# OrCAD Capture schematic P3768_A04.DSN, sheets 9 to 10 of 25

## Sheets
9 0016_USB3.1 Type-A x2 [B]: size Custom
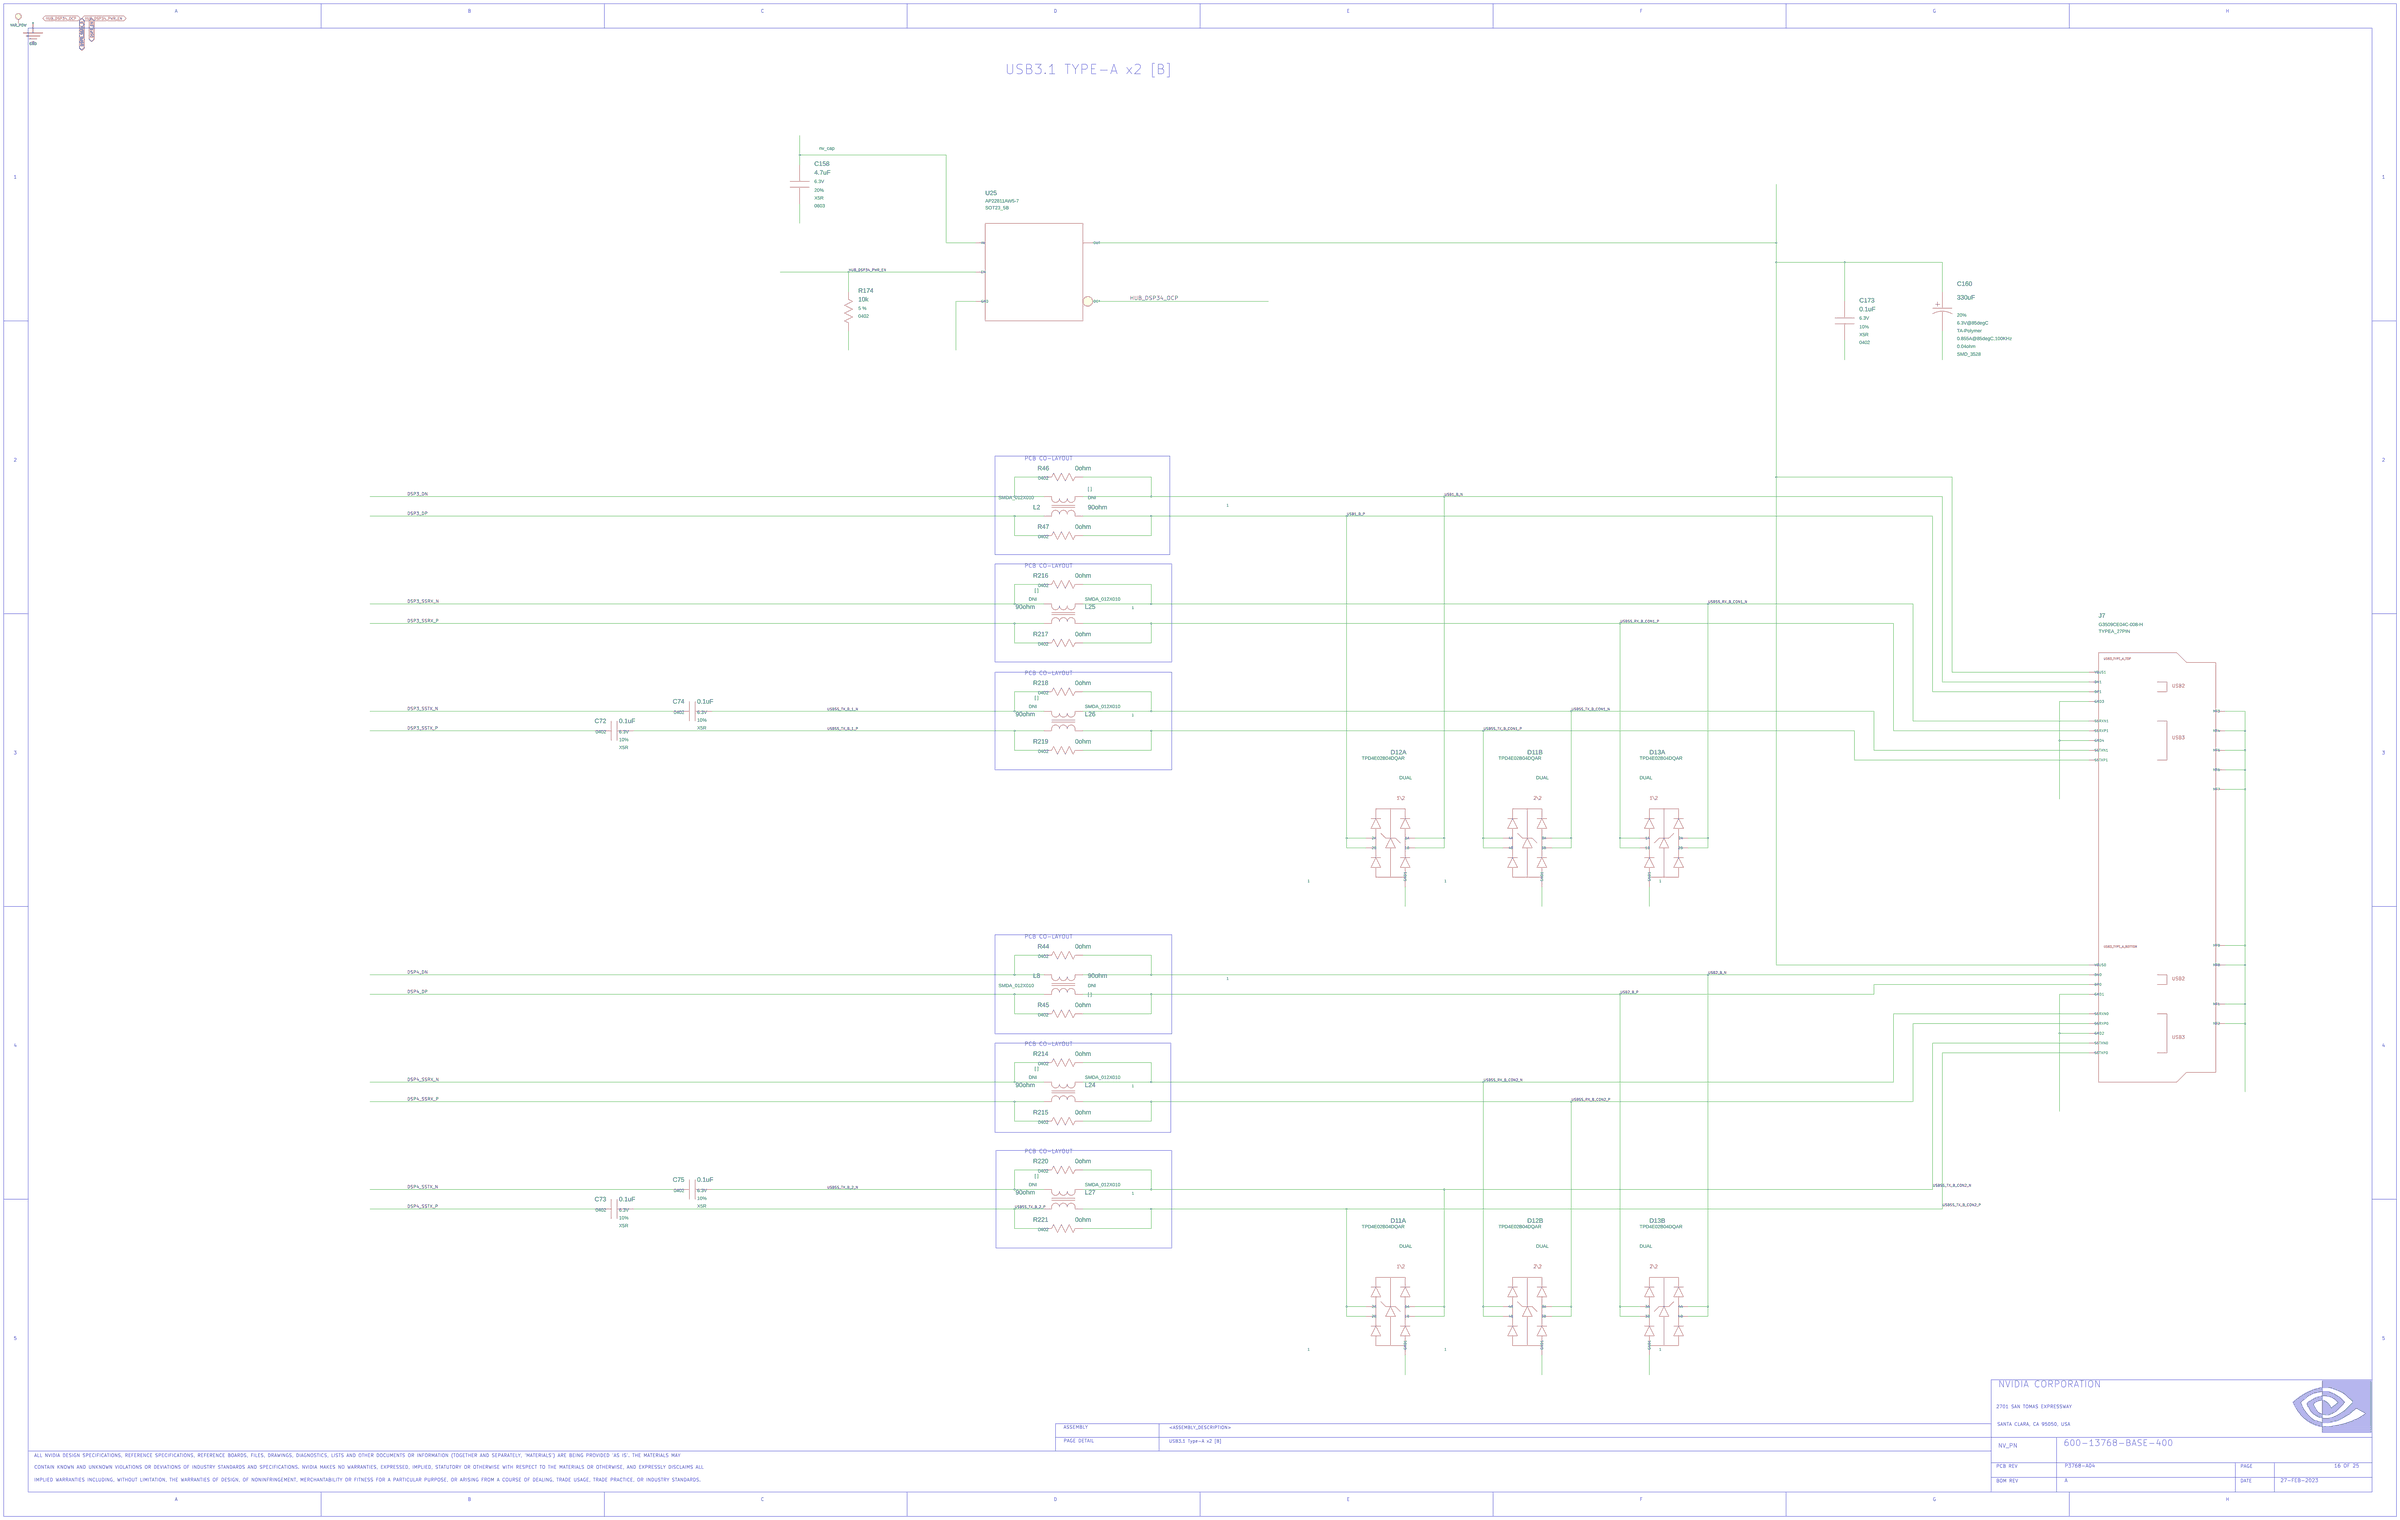
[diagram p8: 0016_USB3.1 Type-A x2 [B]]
10 0015_USB3.1 Type-A x2 [A]: size Custom
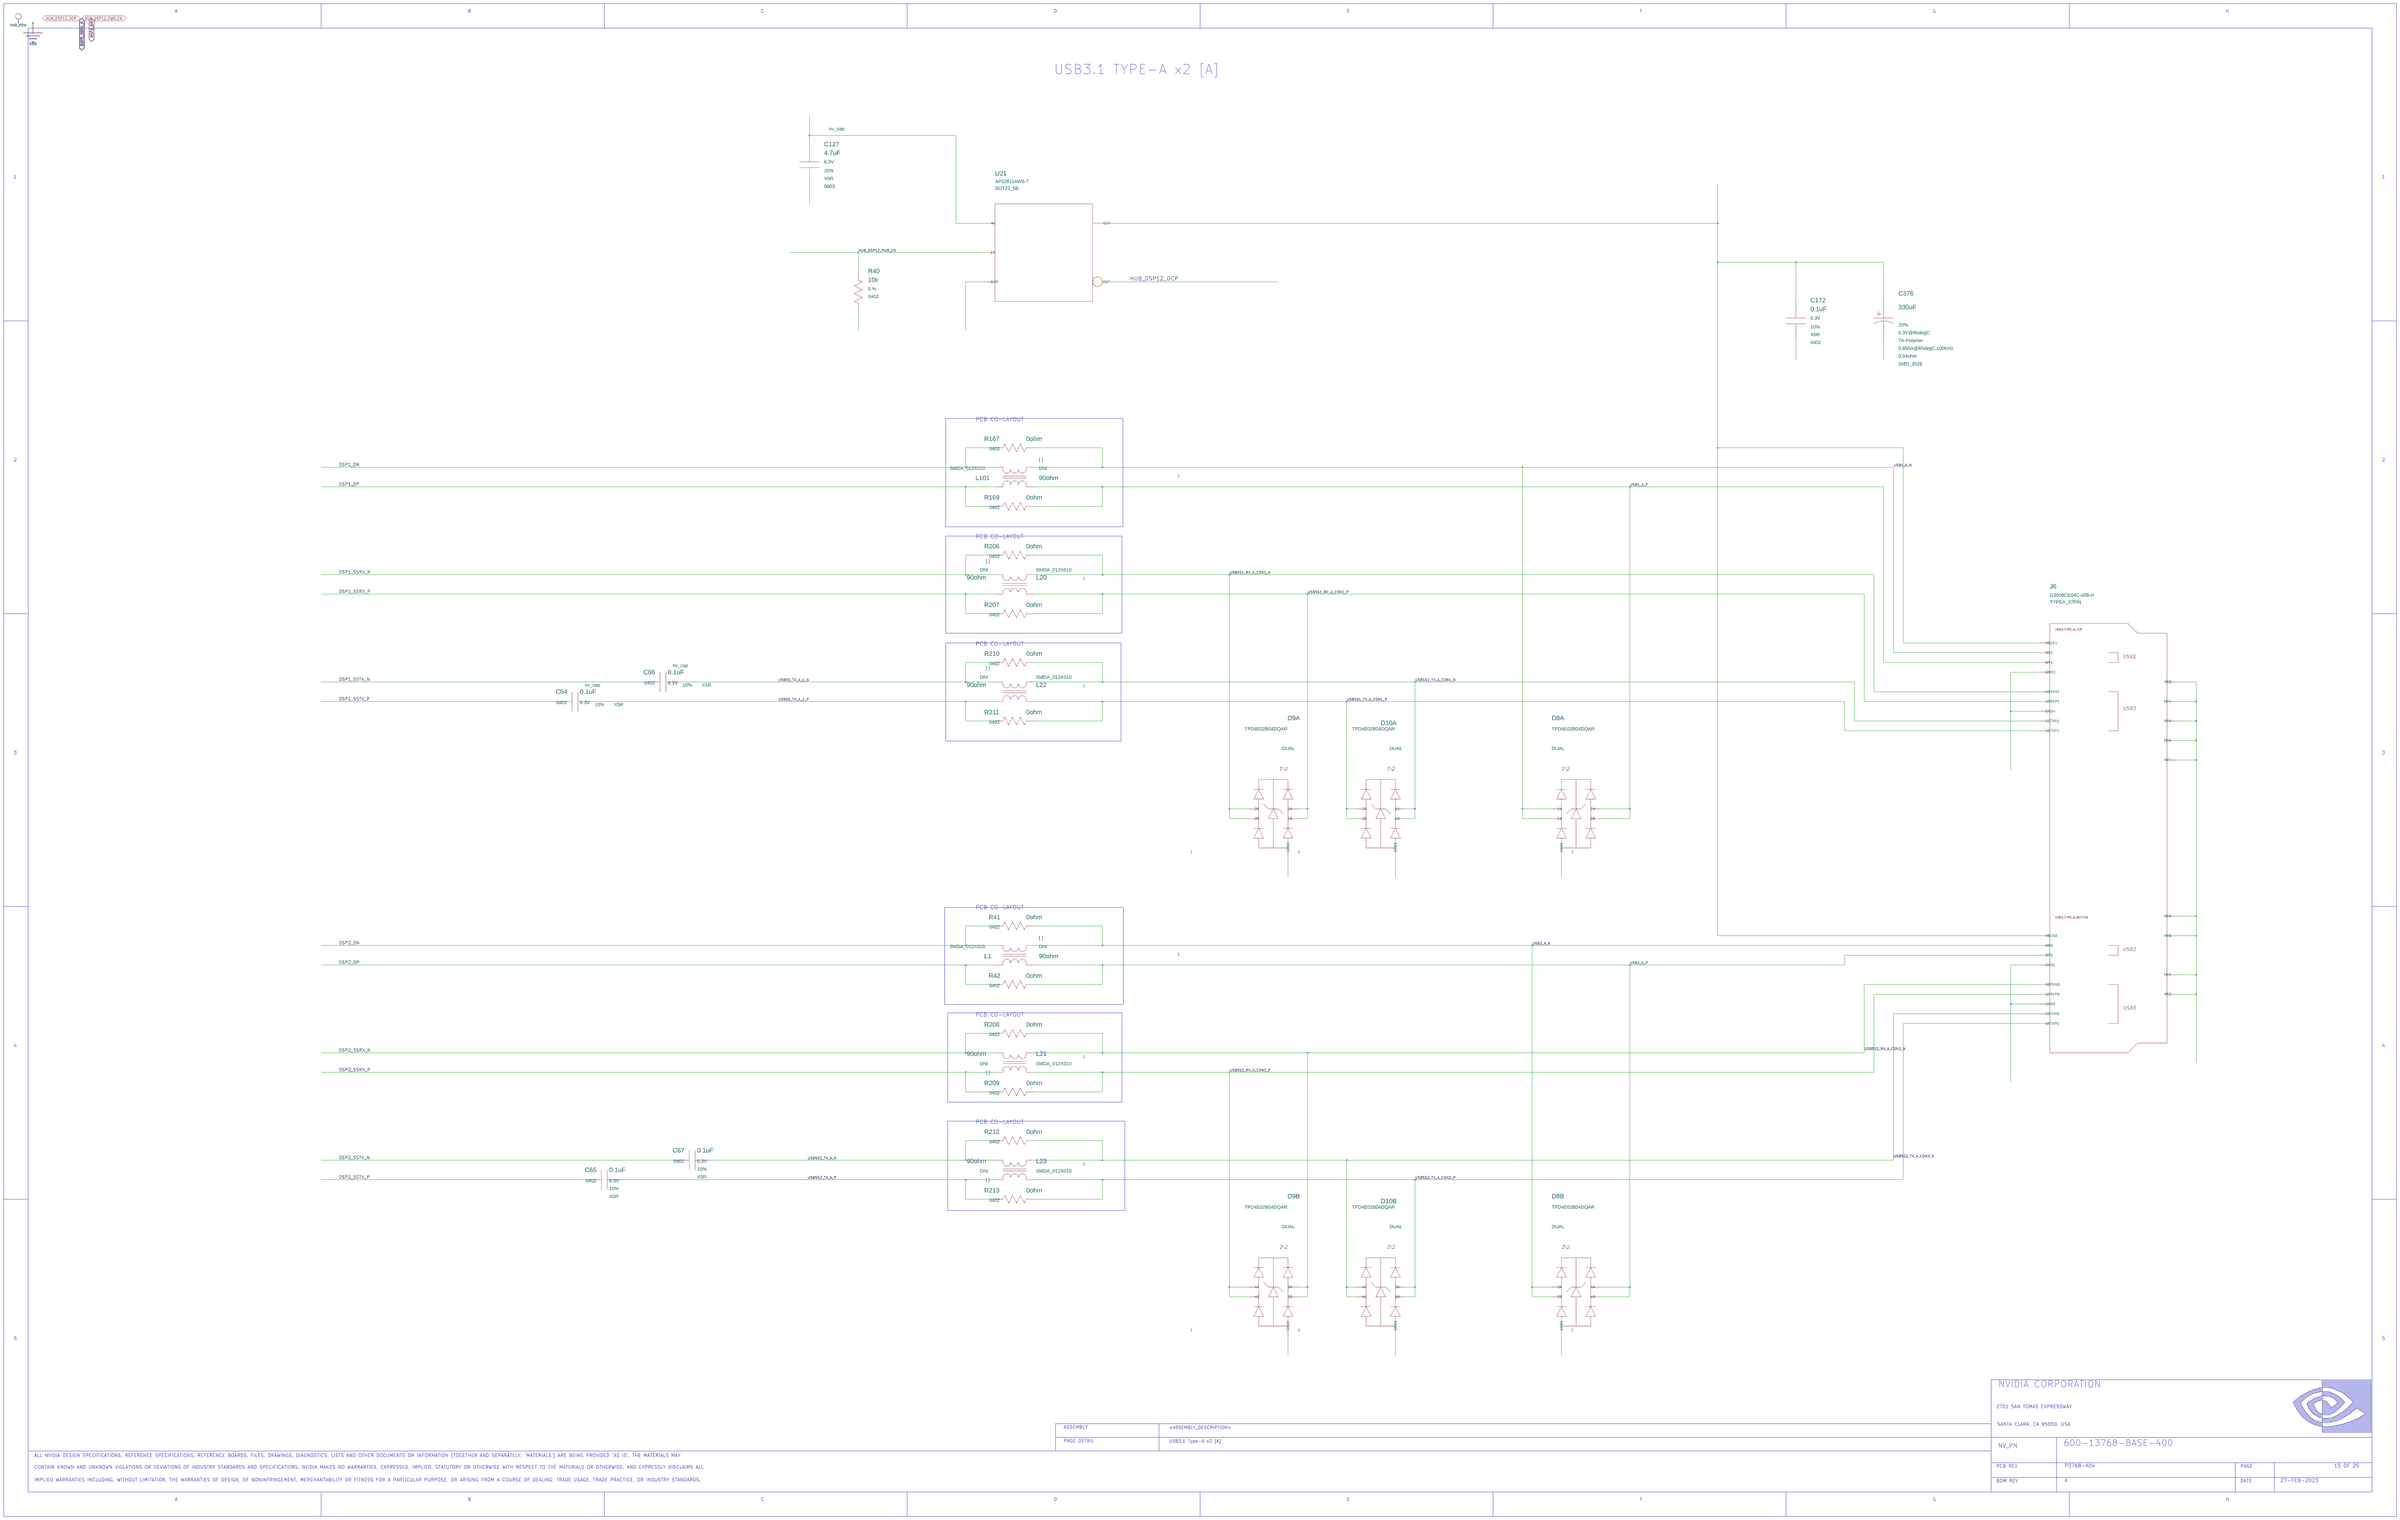
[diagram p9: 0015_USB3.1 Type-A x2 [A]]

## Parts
sheet 0015_USB3.1 Type-A x2 [A]
C64  0.1uF  [0402]
C65  0.1uF  [0402]
C66  0.1uF  [0402]
C67  0.1uF  [0402]
C127  4.7uF  [0603]
C172  0.1uF  [0402]
C376  330uF  [CAP_SMD_3528]
D8  D_ESD_DIFFPAIR  [TSLP10_P050_025X010]  (sections A,B)
D9  D_ESD_DIFFPAIR  [TSLP10_P050_025X010]  (sections A,B)
D10  D_ESD_DIFFPAIR  [TSLP10_P050_025X010]  (sections A,B)
J6  CON_USB3  [CON_USB3_024_SMT_RA_F_138X174]
L1  90ohm  [IND_NONRKO_SMD_012X010]
L20  90ohm  [IND_NONRKO_SMD_012X010]
L21  90ohm  [IND_NONRKO_SMD_012X010]
L22  90ohm  [IND_NONRKO_SMD_012X010]
L23  90ohm  [IND_NONRKO_SMD_012X010]
L101  90ohm  [IND_NONRKO_SMD_012X010]
R40  10k  [0402]
R41  0ohm  [0402]
R42  0ohm  [0402]
R167  0ohm  [0402]
R169  0ohm  [0402]
R206  0ohm  [0402]
R207  0ohm  [0402]
R208  0ohm  [0402]
R209  0ohm  [0402]
R210  0ohm  [0402]
R211  0ohm  [0402]
R212  0ohm  [0402]
R213  0ohm  [0402]
U21  U_SW_LOAD  [SOT23_5_B]
sheet 0016_USB3.1 Type-A x2 [B]
C72  0.1uF  [0402]
C73  0.1uF  [0402]
C74  0.1uF  [0402]
C75  0.1uF  [0402]
C158  4.7uF  [0603]
C160  330uF  [CAP_SMD_3528]
C173  0.1uF  [0402]
D11  D_ESD_DIFFPAIR  [TSLP10_P050_025X010]  (sections A,B)
D12  D_ESD_DIFFPAIR  [TSLP10_P050_025X010]  (sections A,B)
D13  D_ESD_DIFFPAIR  [TSLP10_P050_025X010]  (sections A,B)
J7  CON_USB3  [CON_USB3_024_SMT_RA_F_138X174]
L2  90ohm  [IND_NONRKO_SMD_012X010]
L8  90ohm  [IND_NONRKO_SMD_012X010]
L24  90ohm  [IND_NONRKO_SMD_012X010]
L25  90ohm  [IND_NONRKO_SMD_012X010]
L26  90ohm  [IND_NONRKO_SMD_012X010]
L27  90ohm  [IND_NONRKO_SMD_012X010]
R44  0ohm  [0402]
R45  0ohm  [0402]
R46  0ohm  [0402]
R47  0ohm  [0402]
R174  10k  [0402]
R214  0ohm  [0402]
R215  0ohm  [0402]
R216  0ohm  [0402]
R217  0ohm  [0402]
R218  0ohm  [0402]
R219  0ohm  [0402]
R220  0ohm  [0402]
R221  0ohm  [0402]
U25  U_SW_LOAD  [SOT23_5_B]

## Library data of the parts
C64 = C: ASSEMBLY: USB3_TYPEA; CDS_LIB: discrete; CDS_PART_NAME: C_0402-0.1UF,X5R,10%,6.3V,039-0007-000; CDS_PHYS_PART_NAME: C_0402-0.1UF,X5R,10%,6.3V,039-0007-000-0.1UF,039-0007-000; CDS_SEC: 1; DEVICE_TYPENAME: C_0402-01UFX5R1063V039-0007-000-01UF039-0007-000; DRAWING: @P3768_A04_LIB.P3768_A04(SCH_1):PAGE15; MAT: X5R; MAX_VOLTAGE: 6.3V; NV_PN: 039-0007-000; PATH: I101; PHYS_PAGE: 15; PSPICETEMPLATE: X^@REFDES  %1    %2   @NV_PN; ROT: 0; SEC: 1; SIGNAL_MODEL: nv_cap; TOL: 10%; VER: 2; XY: (-9200,4050)
C65 = C: ASSEMBLY: USB3_TYPEA; CDS_LIB: discrete; CDS_PART_NAME: C_0402-0.1UF,X5R,10%,6.3V,039-0007-000; CDS_PHYS_PART_NAME: C_0402-0.1UF,X5R,10%,6.3V,039-0007-000-0.1UF,039-0007-000; CDS_SEC: 1; DEVICE_TYPENAME: C_0402-01UFX5R1063V039-0007-000-01UF039-0007-000; DRAWING: @P3768_A04_LIB.P3768_A04(SCH_1):PAGE15; MAT: X5R; MAX_VOLTAGE: 6.3V; NV_PN: 039-0007-000; PATH: I91; PHYS_PAGE: 15; ROT: 0; SEC: 1; SIGNAL_MODEL: nv_cap; TOL: 10%; VER: 2; XY: (-9050,1600)
C66 = C: ASSEMBLY: USB3_TYPEA; CDS_LIB: discrete; CDS_PART_NAME: C_0402-0.1UF,X5R,10%,6.3V,039-0007-000; CDS_PHYS_PART_NAME: C_0402-0.1UF,X5R,10%,6.3V,039-0007-000-0.1UF,039-0007-000; CDS_SEC: 1; DEVICE_TYPENAME: C_0402-01UFX5R1063V039-0007-000-01UF039-0007-000; DRAWING: @P3768_A04_LIB.P3768_A04(SCH_1):PAGE15; MAT: X5R; MAX_VOLTAGE: 6.3V; NV_PN: 039-0007-000; PATH: I105; PHYS_PAGE: 15; PSPICETEMPLATE: X^@REFDES  %1    %2   @NV_PN; ROT: 0; SEC: 1; SIGNAL_MODEL: nv_cap; TOL: 10%; VER: 2; XY: (-8750,4150)
C67 = C: ASSEMBLY: USB3_TYPEA; CDS_LIB: discrete; CDS_PART_NAME: C_0402-0.1UF,X5R,10%,6.3V,039-0007-000; CDS_PHYS_PART_NAME: C_0402-0.1UF,X5R,10%,6.3V,039-0007-000-0.1UF,039-0007-000; CDS_SEC: 1; DEVICE_TYPENAME: C_0402-01UFX5R1063V039-0007-000-01UF039-0007-000; DRAWING: @P3768_A04_LIB.P3768_A04(SCH_1):PAGE15; MAT: X5R; MAX_VOLTAGE: 6.3V; NV_PN: 039-0007-000; PATH: I90; PHYS_PAGE: 15; ROT: 0; SEC: 1; SIGNAL_MODEL: nv_cap; TOL: 10%; VER: 2; XY: (-8600,1700)
C127 = C#1: ASSEMBLY: USB3_TYPEA; CDS_LIB: discrete; CDS_PART_NAME: C_0603-4.7UF,X5R,20%,6.3V,032-2124-000; CDS_PHYS_PART_NAME: C_0603-4.7UF,X5R,20%,6.3V,032-2124-000-032-2124-000,4.7UF; CDS_SEC: 1; CHIPS_PART_NAME: C; DEVICE_TYPENAME: C_0603-47UFX5R2063V032-2124-000-032-2124-00047UF; DRAWING: @P3768_A04_LIB.P3768_A04(SCH_1):PAGE15; MAT: X5R; MAX_VOLTAGE: 6.3V; NV_PN: 032-2124-000; PATH: I40; PHYS_PAGE: 15; PSPICETEMPLATE: X^@REFDES  %1    %2   @NV_PN; ROT: 0; SEC: 1; SIGNAL_MODEL: nv_cap; TOL: 20%; VER: 1; XY: (-8000,6800)
C172 = C#1: ASSEMBLY: USB3_TYPEA; CDS_LIB: discrete; CDS_PART_NAME: C_0402-0.1UF,X5R,10%,6.3V,039-0007-000; CDS_PHYS_PART_NAME: C_0402-0.1UF,X5R,10%,6.3V,039-0007-000-0.1UF,039-0007-000; CDS_SEC: 1; CHIPS_PART_NAME: C; DEVICE_TYPENAME: C_0402-01UFX5R1063V039-0007-000-01UF039-0007-000; DRAWING: @P3768_A04_LIB.P3768_A04(SCH_1):PAGE15; MAT: X5R; MAX_VOLTAGE: 6.3V; NV_PN: 039-0007-000; PATH: I65; PHYS_PAGE: 15; PSPICETEMPLATE: X^@REFDES  %1    %2   @NV_PN; ROT: 0; SEC: 1; SIGNAL_MODEL: nv_cap; TOL: 10%; VER: 1; XY: (-2950,6000)
C376 = C_POL: ASSEMBLY: USB3_TYPEA; CDS_LIB: discrete; CDS_PART_NAME: C_POL_SMD_3528-330UF,TA-POLYMER,20%,6.3V@85DEGC,0.04OHM,9.999UH,0.855A@85DEGC,100KHZ,032-0696-000; CDS_PHYS_PART_NAME: C_POL_SMD_3528-330UF,TA-POLYMER,20%,6.3V@85DEGC,0.04OHM,9.999UH,0.855A@85DEGC,100KHZ,032-0696-000-032-0696-000,330UF; CDS_SEC: 1; DEVICE_TYPENAME: C_POL_SMD_3528-330UFTA-POLYMER2063V85DEGC004OHM9999UH0855A85DEGC100KHZ032-0696-000-032-0696-000330UF; DRAWING: @P3768_A04_LIB.P3768_A04(SCH_1):PAGE15; ESL: 9.999uH; ESR: 0.04ohm; MAT: TA-Polymer; MAX_VOLTAGE: 6.3V@85degC; NV_PN: 032-0696-000; PACK_TYPE: SMD_3528; PATH: I99; PHYS_PAGE: 15; PSPICETEMPLATE: X^@REFDES  %1    %2   @NV_PN; RIPPLE_CURRENT: 0.855A@85degC,100KHz; ROT: 0; SEC: 1; SIGNAL_MODEL: nv_capp; TOL: 20%; VER: 1; XY: (-2500,6000)
D8 = D_ESD_DIFFPAIR: ASSEMBLY: USB3_TYPEA; BREAKDOWN_VOLTAGE_MIN_TYP: 6.7V; CAPACITANCE_MAX_TYP: 0.37pF; CDS_LIB: discrete; CDS_PART_NAME: D_ESD_DIFFPAIR_DUAL-TPD4E02B04DQAR,2 DIFFPAIR,BI-DIRECTIONAL,6V,0.01UA,6.7V,8V@40A,0.37PF,090-0296-000; CDS_PHYS_PART_NAME: D_ESD_DIFFPAIR_DUAL-TPD4E02B04DQAR,2 DIFFPAIR,BI-DIRECTIONAL,6V,0.01UA,6.7V,8V@40A,0.37PF,090-0296-000-090-0296-000; CDS_SEC: 1; CLAMPING_VOLTAGE: 8V@40A; CONFIGURATION: 2 Diffpair; CaptureCellPackProp: D_ESD_DIFFPAIRA; DEVICE_TYPENAME: D_ESD_DIFFPAIR_DUAL-TPD4E02B04DQAR2DIFFPAIRBI-DIRECTIONAL6V001UA67V8V40A037PF090-0296-000-090-0296-000; DRAWING: @P3768_A04_LIB.P3768_A04(SCH_1):PAGE15; MAX_REVERSE_LEAKAGE_CURRENT: 0.01uA; MAX_REVERSE_VOLTAGE: 6V; NO_XNET_CONNECTION: 1; NV_NAME: TPD4E02B04DQAR; NV_PN: 090-0296-000; PACK_TYPE: DUAL; PATH: I24; PHYS_PAGE: 15; POLARITY: Bi-Directional; ROT: 0; SEC: 1; SEC_TYPE: DUAL; VER: 1; XY: (-4100,3500)
D9 = D_ESD_DIFFPAIR: ASSEMBLY: USB3_TYPEA; BREAKDOWN_VOLTAGE_MIN_TYP: 6.7V; CAPACITANCE_MAX_TYP: 0.37pF; CDS_LIB: discrete; CDS_PART_NAME: D_ESD_DIFFPAIR_DUAL-TPD4E02B04DQAR,2 DIFFPAIR,BI-DIRECTIONAL,6V,0.01UA,6.7V,8V@40A,0.37PF,090-0296-000; CDS_PHYS_PART_NAME: D_ESD_DIFFPAIR_DUAL-TPD4E02B04DQAR,2 DIFFPAIR,BI-DIRECTIONAL,6V,0.01UA,6.7V,8V@40A,0.37PF,090-0296-000-090-0296-000; CDS_SEC: 1; CLAMPING_VOLTAGE: 8V@40A; CONFIGURATION: 2 Diffpair; CaptureCellPackProp: D_ESD_DIFFPAIRA; DEVICE_TYPENAME: D_ESD_DIFFPAIR_DUAL-TPD4E02B04DQAR2DIFFPAIRBI-DIRECTIONAL6V001UA67V8V40A037PF090-0296-000-090-0296-000; DRAWING: @P3768_A04_LIB.P3768_A04(SCH_1):PAGE15; MAX_REVERSE_LEAKAGE_CURRENT: 0.01uA; MAX_REVERSE_VOLTAGE: 6V; NO_XNET_CONNECTION: 1; NV_NAME: TPD4E02B04DQAR; NV_PN: 090-0296-000; PACK_TYPE: DUAL; PATH: I33; PHYS_PAGE: 15; POLARITY: Bi-Directional; ROT: 2; SEC: 1; VER: 1; XY: (-5600,3500)
D10 = D_ESD_DIFFPAIR: ASSEMBLY: USB3_TYPEA; BREAKDOWN_VOLTAGE_MIN_TYP: 6.7V; CAPACITANCE_MAX_TYP: 0.37pF; CDS_LIB: discrete; CDS_PART_NAME: D_ESD_DIFFPAIR_DUAL-TPD4E02B04DQAR,2 DIFFPAIR,BI-DIRECTIONAL,6V,0.01UA,6.7V,8V@40A,0.37PF,090-0296-000; CDS_PHYS_PART_NAME: D_ESD_DIFFPAIR_DUAL-TPD4E02B04DQAR,2 DIFFPAIR,BI-DIRECTIONAL,6V,0.01UA,6.7V,8V@40A,0.37PF,090-0296-000-090-0296-000; CDS_SEC: 1; CLAMPING_VOLTAGE: 8V@40A; CONFIGURATION: 2 Diffpair; CaptureCellPackProp: D_ESD_DIFFPAIRA; DEVICE_TYPENAME: D_ESD_DIFFPAIR_DUAL-TPD4E02B04DQAR2DIFFPAIRBI-DIRECTIONAL6V001UA67V8V40A037PF090-0296-000-090-0296-000; DRAWING: @P3768_A04_LIB.P3768_A04(SCH_1):PAGE15; MAX_REVERSE_LEAKAGE_CURRENT: 0.01uA; MAX_REVERSE_VOLTAGE: 6V; NO_XNET_CONNECTION: 1; NV_NAME: TPD4E02B04DQAR; NV_PN: 090-0296-000; PACK_TYPE: DUAL; PATH: I27; PHYS_PAGE: 15; POLARITY: Bi-Directional; ROT: 2; SEC: 1; VER: 1; XY: (-5050,3500)
J6 = CON_USB3#1: ANGLE: 90; ASSEMBLY: USB3_TYPEA; CDS_LIB: electro_mechanic; CDS_PART_NAME: CON_USB3_TYPEA_27PIN-G3509CE04C-008-H,RECEPTACLE,2MM,90,YES,YES,YES,NO,YES,30V,1.8 A,065-0738-000; CDS_PHYS_PART_NAME: CON_USB3_TYPEA_27PIN-G3509CE04C-008-H,RECEPTACLE,2MM,90,YES,YES,YES,NO,YES,30V,1.8 A,065-0738-000-065-0738-000; CDS_SEC: 1; DEVICE_TYPENAME: CON_USB3_TYPEA_27PIN-G3509CE04C-008-HRECEPTACLE2MM90YESYESYESNOYES30V18A065-0738-000-065-0738-000; DRAWING: @P3768_A04_LIB.P3768_A04(SCH_1):PAGE15; EMI_GROUND_TAB: NO; GENDER: Receptacle; LATCHING: YES; MAX_CURRENT: 1.8 A; MAX_VOLTAGE: 30v; NV_NAME: G3509CE04C-008-H; NV_PN: 065-0738-000; PACK_TYPE: TYPEA_27PIN; PATH: I80; PHYS_PAGE: 15; PITCH: 2mm; REFLOW: YES; ROT: 0; SEC: 1; SHIELDED: YES; SHROUDED: YES; VER: 14; XY: (-1350,3350)
L1 = L_CMF_4P: ASSEMBLY: USB3_TYPEA; CDS_LIB: discrete; CDS_PART_NAME: L_CMF_4P_SMDA_012X010-90OHM,[ ],25%,0.2A,0.4OHM,[ ],102-0037-000; CDS_PHYS_PART_NAME: L_CMF_4P_SMDA_012X010-90OHM,[ ],25%,0.2A,0.4OHM,[ ],102-0037-000-102-0037-000,90OHM; CDS_SEC: 1; DC_RESISTANCE: 0.4ohm; DEVICE_TYPENAME: L_CMF_4P_SMDA_012X010-90OHM2502A04OHM102-0037-000-102-0037-00090OHM; DRAWING: @P3768_A04_LIB.P3768_A04(SCH_1):PAGE15; MAT: [ ]; MAX_CURRENT: 0.2A; NO_XNET_CONNECTION: 1; NV_NAME: [ ]; NV_PN: 102-0037-000; PACK_TYPE: SMDA_012X010; PATH: I130; PHYS_PAGE: 15; PLACEMENT_NOTE: CoLayout with R167, R169; ROT: 6; SEC: 1; SEC_TYPE: SMDA_012X010; SIGNAL_MODEL: nv_ind_cmf_4p; SKU: DNI; TOL: 25%; VER: 1; XY: (-6950,2750)
L20 = L_CMF_4P: ASSEMBLY: USB3_TYPEA; CDS_LIB: discrete; CDS_PART_NAME: L_CMF_4P_SMDA_012X010-90OHM,[ ],25%,0.2A,0.4OHM,[ ],102-0037-000; CDS_PHYS_PART_NAME: L_CMF_4P_SMDA_012X010-90OHM,[ ],25%,0.2A,0.4OHM,[ ],102-0037-000-102-0037-000,90OHM; CDS_SEC: 1; DC_RESISTANCE: 0.4ohm; DEVICE_TYPENAME: L_CMF_4P_SMDA_012X010-90OHM2502A04OHM102-0037-000-102-0037-00090OHM; DRAWING: @P3768_A04_LIB.P3768_A04(SCH_1):PAGE15; MAT: [ ]; MAX_CURRENT: 0.2A; NO_XNET_CONNECTION: 1; NV_NAME: [ ]; NV_PN: 102-0037-000; PACK_TYPE: SMDA_012X010; PATH: I128; PHYS_PAGE: 15; PLACEMENT_NOTE: CoLayout with R167, R169; ROT: 4; SEC: 1; SEC_TYPE: SMDA_012X010; SIGNAL_MODEL: nv_ind_cmf_4p; SKU: DNI; TOL: 25%; VER: 1; XY: (-6950,4650)
L21 = L_CMF_4P: ASSEMBLY: USB3_TYPEA; CDS_LIB: discrete; CDS_PART_NAME: L_CMF_4P_SMDA_012X010-90OHM,[ ],25%,0.2A,0.4OHM,[ ],102-0037-000; CDS_PHYS_PART_NAME: L_CMF_4P_SMDA_012X010-90OHM,[ ],25%,0.2A,0.4OHM,[ ],102-0037-000-102-0037-000,90OHM; CDS_SEC: 1; DC_RESISTANCE: 0.4ohm; DEVICE_TYPENAME: L_CMF_4P_SMDA_012X010-90OHM2502A04OHM102-0037-000-102-0037-00090OHM; DRAWING: @P3768_A04_LIB.P3768_A04(SCH_1):PAGE15; MAT: [ ]; MAX_CURRENT: 0.2A; NO_XNET_CONNECTION: 1; NV_NAME: [ ]; NV_PN: 102-0037-000; PACK_TYPE: SMDA_012X010; PATH: I131; PHYS_PAGE: 15; PLACEMENT_NOTE: CoLayout with R167, R169; ROT: 2; SEC: 1; SEC_TYPE: SMDA_012X010; SIGNAL_MODEL: nv_ind_cmf_4p; SKU: DNI; TOL: 25%; VER: 1; XY: (-6950,2200)
L22 = L_CMF_4P: ASSEMBLY: USB3_TYPEA; CDS_LIB: discrete; CDS_PART_NAME: L_CMF_4P_SMDA_012X010-90OHM,[ ],25%,0.2A,0.4OHM,[ ],102-0037-000; CDS_PHYS_PART_NAME: L_CMF_4P_SMDA_012X010-90OHM,[ ],25%,0.2A,0.4OHM,[ ],102-0037-000-102-0037-000,90OHM; CDS_SEC: 1; DC_RESISTANCE: 0.4ohm; DEVICE_TYPENAME: L_CMF_4P_SMDA_012X010-90OHM2502A04OHM102-0037-000-102-0037-00090OHM; DRAWING: @P3768_A04_LIB.P3768_A04(SCH_1):PAGE15; MAT: [ ]; MAX_CURRENT: 0.2A; NO_XNET_CONNECTION: 1; NV_NAME: [ ]; NV_PN: 102-0037-000; PACK_TYPE: SMDA_012X010; PATH: I129; PHYS_PAGE: 15; PLACEMENT_NOTE: CoLayout with R167, R169; ROT: 4; SEC: 1; SEC_TYPE: SMDA_012X010; SIGNAL_MODEL: nv_ind_cmf_4p; SKU: DNI; TOL: 25%; VER: 1; XY: (-6950,4100)
L23 = L_CMF_4P: ASSEMBLY: USB3_TYPEA; CDS_LIB: discrete; CDS_PART_NAME: L_CMF_4P_SMDA_012X010-90OHM,[ ],25%,0.2A,0.4OHM,[ ],102-0037-000; CDS_PHYS_PART_NAME: L_CMF_4P_SMDA_012X010-90OHM,[ ],25%,0.2A,0.4OHM,[ ],102-0037-000-102-0037-000,90OHM; CDS_SEC: 1; DC_RESISTANCE: 0.4ohm; DEVICE_TYPENAME: L_CMF_4P_SMDA_012X010-90OHM2502A04OHM102-0037-000-102-0037-00090OHM; DRAWING: @P3768_A04_LIB.P3768_A04(SCH_1):PAGE15; MAT: [ ]; MAX_CURRENT: 0.2A; NO_XNET_CONNECTION: 1; NV_NAME: [ ]; NV_PN: 102-0037-000; PACK_TYPE: SMDA_012X010; PATH: I132; PHYS_PAGE: 15; PLACEMENT_NOTE: CoLayout with R167, R169; ROT: 2; SEC: 1; SEC_TYPE: SMDA_012X010; SIGNAL_MODEL: nv_ind_cmf_4p; SKU: DNI; TOL: 25%; VER: 1; XY: (-6950,1650)
L101 = L_CMF_4P: ASSEMBLY: USB3_TYPEA; CDS_LIB: discrete; CDS_PART_NAME: L_CMF_4P_SMDA_012X010-90OHM,[ ],25%,0.2A,0.4OHM,[ ],102-0037-000; CDS_PHYS_PART_NAME: L_CMF_4P_SMDA_012X010-90OHM,[ ],25%,0.2A,0.4OHM,[ ],102-0037-000-102-0037-000,90OHM; CDS_SEC: 1; DC_RESISTANCE: 0.4ohm; DEVICE_TYPENAME: L_CMF_4P_SMDA_012X010-90OHM2502A04OHM102-0037-000-102-0037-00090OHM; DRAWING: @P3768_A04_LIB.P3768_A04(SCH_1):PAGE15; MAT: [ ]; MAX_CURRENT: 0.2A; NO_XNET_CONNECTION: 1; NV_NAME: [ ]; NV_PN: 102-0037-000; PACK_TYPE: SMDA_012X010; PATH: I127; PHYS_PAGE: 15; PLACEMENT_NOTE: CoLayout with R167, R169; ROT: 6; SEC: 1; SEC_TYPE: SMDA_012X010; SIGNAL_MODEL: nv_ind_cmf_4p; SKU: DNI; TOL: 25%; VER: 1; XY: (-6950,5200)
R40 = R: ASSEMBLY: USB3_TYPEA; CDS_LIB: discrete; CDS_PART_NAME: R_0402-10K,5 %,62.5MW,195-0486-000; CDS_PHYS_PART_NAME: R_0402-10K,5 %,62.5MW,195-0486-000-10K,195-0486-000; CDS_SEC: 1; DEVICE_TYPENAME: R_0402-10K5625MW195-0486-000-10K195-0486-000; DRAWING: @P3768_A04_LIB.P3768_A04(SCH_1):PAGE15; MAX_WATTAGE: 62.5mW; NV_PN: 195-0486-000; PATH: I42; PHYS_PAGE: 15; PSPICETEMPLATE: X^@REFDES  %1    %2   @NV_PN; ROT: 0; SEC: 1; SIGNAL_MODEL: nv_res; TOL: 5 %; VER: 2; XY: (-7750,6150)
R41 = R#1: ASSEMBLY: USB3_TYPEA; CDS_LIB: discrete; CDS_PART_NAME: R_0402-0OHM,0.05 OHM,62.5MW,195-2655-000; CDS_PHYS_PART_NAME: R_0402-0OHM,0.05 OHM,62.5MW,195-2655-000-0OHM,195-2655-000; CDS_SEC: 1; CHIPS_PART_NAME: R; DEVICE_TYPENAME: R_0402-0OHM005OHM625MW195-2655-000-0OHM195-2655-000; DRAWING: @P3768_A04_LIB.P3768_A04(SCH_1):PAGE15; MAX_WATTAGE: 62.5mW; NV_PN: 195-2655-000; PATH: I118; PHYS_PAGE: 15; PLACEMENT_NOTE: CoLayout with L10; ROT: 0; SEC: 1; SIGNAL_MODEL: DEFAULT_RESISTOR_0.001OHM_2_1; TOL: 0.05 ohm; VER: 1; XY: (-6950,2900)
R42 = R#1: ASSEMBLY: USB3_TYPEA; CDS_LIB: discrete; CDS_PART_NAME: R_0402-0OHM,0.05 OHM,62.5MW,195-2655-000; CDS_PHYS_PART_NAME: R_0402-0OHM,0.05 OHM,62.5MW,195-2655-000-0OHM,195-2655-000; CDS_SEC: 1; CHIPS_PART_NAME: R; DEVICE_TYPENAME: R_0402-0OHM005OHM625MW195-2655-000-0OHM195-2655-000; DRAWING: @P3768_A04_LIB.P3768_A04(SCH_1):PAGE15; MAX_WATTAGE: 62.5mW; NV_PN: 195-2655-000; PATH: I120; PHYS_PAGE: 15; PLACEMENT_NOTE: CoLayout with L10; ROT: 0; SEC: 1; SIGNAL_MODEL: DEFAULT_RESISTOR_0.001OHM_2_1; TOL: 0.05 ohm; VER: 1; XY: (-6950,2600)
R167 = R#1: ASSEMBLY: USB3_TYPEA; CDS_LIB: discrete; CDS_PART_NAME: R_0402-0OHM,0.05 OHM,62.5MW,195-2655-000; CDS_PHYS_PART_NAME: R_0402-0OHM,0.05 OHM,62.5MW,195-2655-000-0OHM,195-2655-000; CDS_SEC: 1; CHIPS_PART_NAME: R; DEVICE_TYPENAME: R_0402-0OHM005OHM625MW195-2655-000-0OHM195-2655-000; DRAWING: @P3768_A04_LIB.P3768_A04(SCH_1):PAGE15; MAX_WATTAGE: 62.5mW; NV_PN: 195-2655-000; PATH: I110; PHYS_PAGE: 15; PLACEMENT_NOTE: CoLayout with L10; ROT: 0; SEC: 1; SIGNAL_MODEL: DEFAULT_RESISTOR_0.001OHM_2_1; TOL: 0.05 ohm; VER: 1; XY: (-6950,5350)
R169 = R#1: ASSEMBLY: USB3_TYPEA; CDS_LIB: discrete; CDS_PART_NAME: R_0402-0OHM,0.05 OHM,62.5MW,195-2655-000; CDS_PHYS_PART_NAME: R_0402-0OHM,0.05 OHM,62.5MW,195-2655-000-0OHM,195-2655-000; CDS_SEC: 1; CHIPS_PART_NAME: R; DEVICE_TYPENAME: R_0402-0OHM005OHM625MW195-2655-000-0OHM195-2655-000; DRAWING: @P3768_A04_LIB.P3768_A04(SCH_1):PAGE15; MAX_WATTAGE: 62.5mW; NV_PN: 195-2655-000; PATH: I111; PHYS_PAGE: 15; PLACEMENT_NOTE: CoLayout with L10; ROT: 0; SEC: 1; SIGNAL_MODEL: DEFAULT_RESISTOR_0.001OHM_2_1; TOL: 0.05 ohm; VER: 1; XY: (-6950,5050)
R206 = R#1: ASSEMBLY: USB3_TYPEA; CDS_LIB: discrete; CDS_PART_NAME: R_0402-0OHM,0.05 OHM,62.5MW,195-2655-000; CDS_PHYS_PART_NAME: R_0402-0OHM,0.05 OHM,62.5MW,195-2655-000-0OHM,195-2655-000; CDS_SEC: 1; CHIPS_PART_NAME: R; DEVICE_TYPENAME: R_0402-0OHM005OHM625MW195-2655-000-0OHM195-2655-000; DRAWING: @P3768_A04_LIB.P3768_A04(SCH_1):PAGE15; MAX_WATTAGE: 62.5mW; NV_PN: 195-2655-000; PATH: I112; PHYS_PAGE: 15; PLACEMENT_NOTE: CoLayout with L10; ROT: 0; SEC: 1; SIGNAL_MODEL: DEFAULT_RESISTOR_0.001OHM_2_1; TOL: 0.05 ohm; VER: 1; XY: (-6950,4800)
R207 = R#1: ASSEMBLY: USB3_TYPEA; CDS_LIB: discrete; CDS_PART_NAME: R_0402-0OHM,0.05 OHM,62.5MW,195-2655-000; CDS_PHYS_PART_NAME: R_0402-0OHM,0.05 OHM,62.5MW,195-2655-000-0OHM,195-2655-000; CDS_SEC: 1; CHIPS_PART_NAME: R; DEVICE_TYPENAME: R_0402-0OHM005OHM625MW195-2655-000-0OHM195-2655-000; DRAWING: @P3768_A04_LIB.P3768_A04(SCH_1):PAGE15; MAX_WATTAGE: 62.5mW; NV_PN: 195-2655-000; PATH: I114; PHYS_PAGE: 15; PLACEMENT_NOTE: CoLayout with L10; ROT: 0; SEC: 1; SIGNAL_MODEL: DEFAULT_RESISTOR_0.001OHM_2_1; TOL: 0.05 ohm; VER: 1; XY: (-6950,4500)
R208 = R#1: ASSEMBLY: USB3_TYPEA; CDS_LIB: discrete; CDS_PART_NAME: R_0402-0OHM,0.05 OHM,62.5MW,195-2655-000; CDS_PHYS_PART_NAME: R_0402-0OHM,0.05 OHM,62.5MW,195-2655-000-0OHM,195-2655-000; CDS_SEC: 1; CHIPS_PART_NAME: R; DEVICE_TYPENAME: R_0402-0OHM005OHM625MW195-2655-000-0OHM195-2655-000; DRAWING: @P3768_A04_LIB.P3768_A04(SCH_1):PAGE15; MAX_WATTAGE: 62.5mW; NV_PN: 195-2655-000; PATH: I121; PHYS_PAGE: 15; PLACEMENT_NOTE: CoLayout with L10; ROT: 0; SEC: 1; SIGNAL_MODEL: DEFAULT_RESISTOR_0.001OHM_2_1; TOL: 0.05 ohm; VER: 1; XY: (-6950,2350)
R209 = R#1: ASSEMBLY: USB3_TYPEA; CDS_LIB: discrete; CDS_PART_NAME: R_0402-0OHM,0.05 OHM,62.5MW,195-2655-000; CDS_PHYS_PART_NAME: R_0402-0OHM,0.05 OHM,62.5MW,195-2655-000-0OHM,195-2655-000; CDS_SEC: 1; CHIPS_PART_NAME: R; DEVICE_TYPENAME: R_0402-0OHM005OHM625MW195-2655-000-0OHM195-2655-000; DRAWING: @P3768_A04_LIB.P3768_A04(SCH_1):PAGE15; MAX_WATTAGE: 62.5mW; NV_PN: 195-2655-000; PATH: I123; PHYS_PAGE: 15; PLACEMENT_NOTE: CoLayout with L10; ROT: 0; SEC: 1; SIGNAL_MODEL: DEFAULT_RESISTOR_0.001OHM_2_1; TOL: 0.05 ohm; VER: 1; XY: (-6950,2050)
R210 = R#1: ASSEMBLY: USB3_TYPEA; CDS_LIB: discrete; CDS_PART_NAME: R_0402-0OHM,0.05 OHM,62.5MW,195-2655-000; CDS_PHYS_PART_NAME: R_0402-0OHM,0.05 OHM,62.5MW,195-2655-000-0OHM,195-2655-000; CDS_SEC: 1; CHIPS_PART_NAME: R; DEVICE_TYPENAME: R_0402-0OHM005OHM625MW195-2655-000-0OHM195-2655-000; DRAWING: @P3768_A04_LIB.P3768_A04(SCH_1):PAGE15; MAX_WATTAGE: 62.5mW; NV_PN: 195-2655-000; PATH: I115; PHYS_PAGE: 15; PLACEMENT_NOTE: CoLayout with L10; ROT: 0; SEC: 1; SIGNAL_MODEL: DEFAULT_RESISTOR_0.001OHM_2_1; TOL: 0.05 ohm; VER: 1; XY: (-6950,4250)
R211 = R#1: ASSEMBLY: USB3_TYPEA; CDS_LIB: discrete; CDS_PART_NAME: R_0402-0OHM,0.05 OHM,62.5MW,195-2655-000; CDS_PHYS_PART_NAME: R_0402-0OHM,0.05 OHM,62.5MW,195-2655-000-0OHM,195-2655-000; CDS_SEC: 1; CHIPS_PART_NAME: R; DEVICE_TYPENAME: R_0402-0OHM005OHM625MW195-2655-000-0OHM195-2655-000; DRAWING: @P3768_A04_LIB.P3768_A04(SCH_1):PAGE15; MAX_WATTAGE: 62.5mW; NV_PN: 195-2655-000; PATH: I117; PHYS_PAGE: 15; PLACEMENT_NOTE: CoLayout with L10; ROT: 0; SEC: 1; SIGNAL_MODEL: DEFAULT_RESISTOR_0.001OHM_2_1; TOL: 0.05 ohm; VER: 1; XY: (-6950,3950)
R212 = R#1: ASSEMBLY: USB3_TYPEA; CDS_LIB: discrete; CDS_PART_NAME: R_0402-0OHM,0.05 OHM,62.5MW,195-2655-000; CDS_PHYS_PART_NAME: R_0402-0OHM,0.05 OHM,62.5MW,195-2655-000-0OHM,195-2655-000; CDS_SEC: 1; CHIPS_PART_NAME: R; DEVICE_TYPENAME: R_0402-0OHM005OHM625MW195-2655-000-0OHM195-2655-000; DRAWING: @P3768_A04_LIB.P3768_A04(SCH_1):PAGE15; MAX_WATTAGE: 62.5mW; NV_PN: 195-2655-000; PATH: I124; PHYS_PAGE: 15; PLACEMENT_NOTE: CoLayout with L10; ROT: 0; SEC: 1; SIGNAL_MODEL: DEFAULT_RESISTOR_0.001OHM_2_1; TOL: 0.05 ohm; VER: 1; XY: (-6950,1800)
R213 = R#1: ASSEMBLY: USB3_TYPEA; CDS_LIB: discrete; CDS_PART_NAME: R_0402-0OHM,0.05 OHM,62.5MW,195-2655-000; CDS_PHYS_PART_NAME: R_0402-0OHM,0.05 OHM,62.5MW,195-2655-000-0OHM,195-2655-000; CDS_SEC: 1; CHIPS_PART_NAME: R; DEVICE_TYPENAME: R_0402-0OHM005OHM625MW195-2655-000-0OHM195-2655-000; DRAWING: @P3768_A04_LIB.P3768_A04(SCH_1):PAGE15; MAX_WATTAGE: 62.5mW; NV_PN: 195-2655-000; PATH: I126; PHYS_PAGE: 15; PLACEMENT_NOTE: CoLayout with L10; ROT: 0; SEC: 1; SIGNAL_MODEL: DEFAULT_RESISTOR_0.001OHM_2_1; TOL: 0.05 ohm; VER: 1; XY: (-6950,1500)
U21 = U_SW_LOAD: ASSEMBLY: USB3_TYPEA; CDS_LIB: analog; CDS_PART_NAME: U_SW_LOAD_SOT23_5B-AP22811AW5-7,0MV..5.5V,2.7V..5.5V,9999A,SWITCH,115-2766-000; CDS_PHYS_PART_NAME: U_SW_LOAD_SOT23_5B-AP22811AW5-7,0MV..5.5V,2.7V..5.5V,9999A,SWITCH,115-2766-000-115-2766-000; CDS_SEC: 1; DEVICE_TYPENAME: U_SW_LOAD_SOT23_5B-AP22811AW5-70MV55V27V55V9999ASWITCH115-2766-000-115-2766-000; DRAWING: @P3768_A04_LIB.P3768_A04(SCH_1):PAGE15; MAX_CURRENT: 9999A; MAX_VOLTAGE: 2.7V..5.5V; NV_NAME: AP22811AW5-7; NV_PN: 115-2766-000; OUTPUT_VOLTAGE: 0mV..5.5V; PACK_TYPE: SOT23_5B; PATH: I81; PHYS_PAGE: 15; ROT: 0; SEC: 1; TYPE: Switch; VER: 7; XY: (-6800,6350)
C72 = C: ASSEMBLY: USB3_TYPEA; CDS_LIB: discrete; CDS_PART_NAME: C_0402-0.1UF,X5R,10%,6.3V,039-0007-000; CDS_PHYS_PART_NAME: C_0402-0.1UF,X5R,10%,6.3V,039-0007-000-0.1UF,039-0007-000; CDS_SEC: 1; DEVICE_TYPENAME: C_0402-01UFX5R1063V039-0007-000-01UF039-0007-000; DRAWING: @P3768_A04_LIB.P3768_A04(SCH_1):PAGE16; MAT: X5R; MAX_VOLTAGE: 6.3V; NV_PN: 039-0007-000; PATH: I69; PHYS_PAGE: 16; ROT: 0; SEC: 1; SIGNAL_MODEL: nv_cap; TOL: 10%; VER: 2; XY: (-9000,3900)
C73 = C: ASSEMBLY: USB3_TYPEA; CDS_LIB: discrete; CDS_PART_NAME: C_0402-0.1UF,X5R,10%,6.3V,039-0007-000; CDS_PHYS_PART_NAME: C_0402-0.1UF,X5R,10%,6.3V,039-0007-000-0.1UF,039-0007-000; CDS_SEC: 1; DEVICE_TYPENAME: C_0402-01UFX5R1063V039-0007-000-01UF039-0007-000; DRAWING: @P3768_A04_LIB.P3768_A04(SCH_1):PAGE16; MAT: X5R; MAX_VOLTAGE: 6.3V; NV_PN: 039-0007-000; PATH: I72; PHYS_PAGE: 16; ROT: 0; SEC: 1; SIGNAL_MODEL: nv_cap; TOL: 10%; VER: 2; XY: (-9000,1450)
C74 = C: ASSEMBLY: USB3_TYPEA; CDS_LIB: discrete; CDS_PART_NAME: C_0402-0.1UF,X5R,10%,6.3V,039-0007-000; CDS_PHYS_PART_NAME: C_0402-0.1UF,X5R,10%,6.3V,039-0007-000-0.1UF,039-0007-000; CDS_SEC: 1; DEVICE_TYPENAME: C_0402-01UFX5R1063V039-0007-000-01UF039-0007-000; DRAWING: @P3768_A04_LIB.P3768_A04(SCH_1):PAGE16; MAT: X5R; MAX_VOLTAGE: 6.3V; NV_PN: 039-0007-000; PATH: I70; PHYS_PAGE: 16; ROT: 0; SEC: 1; SIGNAL_MODEL: nv_cap; TOL: 10%; VER: 2; XY: (-8600,4000)
C75 = C: ASSEMBLY: USB3_TYPEA; CDS_LIB: discrete; CDS_PART_NAME: C_0402-0.1UF,X5R,10%,6.3V,039-0007-000; CDS_PHYS_PART_NAME: C_0402-0.1UF,X5R,10%,6.3V,039-0007-000-0.1UF,039-0007-000; CDS_SEC: 1; DEVICE_TYPENAME: C_0402-01UFX5R1063V039-0007-000-01UF039-0007-000; DRAWING: @P3768_A04_LIB.P3768_A04(SCH_1):PAGE16; MAT: X5R; MAX_VOLTAGE: 6.3V; NV_PN: 039-0007-000; PATH: I71; PHYS_PAGE: 16; ROT: 0; SEC: 1; SIGNAL_MODEL: nv_cap; TOL: 10%; VER: 2; XY: (-8600,1550)
C158 = C#1: ASSEMBLY: USB3_TYPEA; CDS_LIB: discrete; CDS_PART_NAME: C_0603-4.7UF,X5R,20%,6.3V,032-2124-000; CDS_PHYS_PART_NAME: C_0603-4.7UF,X5R,20%,6.3V,032-2124-000-032-2124-000,4.7UF; CDS_SEC: 1; CHIPS_PART_NAME: C; DEVICE_TYPENAME: C_0603-47UFX5R2063V032-2124-000-032-2124-00047UF; DRAWING: @P3768_A04_LIB.P3768_A04(SCH_1):PAGE16; MAT: X5R; MAX_VOLTAGE: 6.3V; NV_PN: 032-2124-000; PATH: I45; PHYS_PAGE: 16; PSPICETEMPLATE: X^@REFDES  %1    %2   @NV_PN; ROT: 0; SEC: 1; SIGNAL_MODEL: nv_cap; TOL: 20%; VER: 1; XY: (-8050,6700)
C160 = C_POL: ASSEMBLY: USB3_TYPEA; CDS_LIB: discrete; CDS_PART_NAME: C_POL_SMD_3528-330UF,TA-POLYMER,20%,6.3V@85DEGC,0.04OHM,9.999UH,0.855A@85DEGC,100KHZ,032-0696-000; CDS_PHYS_PART_NAME: C_POL_SMD_3528-330UF,TA-POLYMER,20%,6.3V@85DEGC,0.04OHM,9.999UH,0.855A@85DEGC,100KHZ,032-0696-000-032-0696-000,330UF; CDS_SEC: 1; DEVICE_TYPENAME: C_POL_SMD_3528-330UFTA-POLYMER2063V85DEGC004OHM9999UH0855A85DEGC100KHZ032-0696-000-032-0696-000330UF; DRAWING: @P3768_A04_LIB.P3768_A04(SCH_1):PAGE16; ESL: 9.999uH; ESR: 0.04ohm; MAT: TA-Polymer; MAX_VOLTAGE: 6.3V@85degC; NV_PN: 032-0696-000; PACK_TYPE: SMD_3528; PATH: I51; PHYS_PAGE: 16; PSPICETEMPLATE: X^@REFDES  %1    %2   @NV_PN; RIPPLE_CURRENT: 0.855A@85degC,100KHz; ROT: 0; SEC: 1; SIGNAL_MODEL: nv_capp; TOL: 20%; VER: 1; XY: (-2200,6050)
C173 = C#1: ASSEMBLY: USB3_TYPEA; CDS_LIB: discrete; CDS_PART_NAME: C_0402-0.1UF,X5R,10%,6.3V,039-0007-000; CDS_PHYS_PART_NAME: C_0402-0.1UF,X5R,10%,6.3V,039-0007-000-0.1UF,039-0007-000; CDS_SEC: 1; CHIPS_PART_NAME: C; DEVICE_TYPENAME: C_0402-01UFX5R1063V039-0007-000-01UF039-0007-000; DRAWING: @P3768_A04_LIB.P3768_A04(SCH_1):PAGE16; MAT: X5R; MAX_VOLTAGE: 6.3V; NV_PN: 039-0007-000; PATH: I53; PHYS_PAGE: 16; PSPICETEMPLATE: X^@REFDES  %1    %2   @NV_PN; ROT: 0; SEC: 1; SIGNAL_MODEL: nv_cap; TOL: 10%; VER: 1; XY: (-2700,6000)
D11 = D_ESD_DIFFPAIR: ASSEMBLY: USB3_TYPEA; BREAKDOWN_VOLTAGE_MIN_TYP: 6.7V; CAPACITANCE_MAX_TYP: 0.37pF; CDS_LIB: discrete; CDS_PART_NAME: D_ESD_DIFFPAIR_DUAL-TPD4E02B04DQAR,2 DIFFPAIR,BI-DIRECTIONAL,6V,0.01UA,6.7V,8V@40A,0.37PF,090-0296-000; CDS_PHYS_PART_NAME: D_ESD_DIFFPAIR_DUAL-TPD4E02B04DQAR,2 DIFFPAIR,BI-DIRECTIONAL,6V,0.01UA,6.7V,8V@40A,0.37PF,090-0296-000-090-0296-000; CDS_SEC: 1; CLAMPING_VOLTAGE: 8V@40A; CONFIGURATION: 2 Diffpair; CaptureCellPackProp: D_ESD_DIFFPAIRA; DEVICE_TYPENAME: D_ESD_DIFFPAIR_DUAL-TPD4E02B04DQAR2DIFFPAIRBI-DIRECTIONAL6V001UA67V8V40A037PF090-0296-000-090-0296-000; DRAWING: @P3768_A04_LIB.P3768_A04(SCH_1):PAGE16; MAX_REVERSE_LEAKAGE_CURRENT: 0.01uA; MAX_REVERSE_VOLTAGE: 6V; NO_XNET_CONNECTION: 1; NV_NAME: TPD4E02B04DQAR; NV_PN: 090-0296-000; PACK_TYPE: DUAL; PATH: I22; PHYS_PAGE: 16; POLARITY: Bi-Directional; ROT: 2; SEC: 1; VER: 1; XY: (-5000,950)
D12 = D_ESD_DIFFPAIR: ASSEMBLY: USB3_TYPEA; BREAKDOWN_VOLTAGE_MIN_TYP: 6.7V; CAPACITANCE_MAX_TYP: 0.37pF; CDS_LIB: discrete; CDS_PART_NAME: D_ESD_DIFFPAIR_DUAL-TPD4E02B04DQAR,2 DIFFPAIR,BI-DIRECTIONAL,6V,0.01UA,6.7V,8V@40A,0.37PF,090-0296-000; CDS_PHYS_PART_NAME: D_ESD_DIFFPAIR_DUAL-TPD4E02B04DQAR,2 DIFFPAIR,BI-DIRECTIONAL,6V,0.01UA,6.7V,8V@40A,0.37PF,090-0296-000-090-0296-000; CDS_SEC: 1; CLAMPING_VOLTAGE: 8V@40A; CONFIGURATION: 2 Diffpair; CaptureCellPackProp: D_ESD_DIFFPAIRA; DEVICE_TYPENAME: D_ESD_DIFFPAIR_DUAL-TPD4E02B04DQAR2DIFFPAIRBI-DIRECTIONAL6V001UA67V8V40A037PF090-0296-000-090-0296-000; DRAWING: @P3768_A04_LIB.P3768_A04(SCH_1):PAGE16; MAX_REVERSE_LEAKAGE_CURRENT: 0.01uA; MAX_REVERSE_VOLTAGE: 6V; NO_XNET_CONNECTION: 1; NV_NAME: TPD4E02B04DQAR; NV_PN: 090-0296-000; PACK_TYPE: DUAL; PATH: I11; PHYS_PAGE: 16; POLARITY: Bi-Directional; ROT: 2; SEC: 1; VER: 1; XY: (-5000,3350)
D13 = D_ESD_DIFFPAIR: ASSEMBLY: USB3_TYPEA; BREAKDOWN_VOLTAGE_MIN_TYP: 6.7V; CAPACITANCE_MAX_TYP: 0.37pF; CDS_LIB: discrete; CDS_PART_NAME: D_ESD_DIFFPAIR_DUAL-TPD4E02B04DQAR,2 DIFFPAIR,BI-DIRECTIONAL,6V,0.01UA,6.7V,8V@40A,0.37PF,090-0296-000; CDS_PHYS_PART_NAME: D_ESD_DIFFPAIR_DUAL-TPD4E02B04DQAR,2 DIFFPAIR,BI-DIRECTIONAL,6V,0.01UA,6.7V,8V@40A,0.37PF,090-0296-000-090-0296-000; CDS_SEC: 2; CLAMPING_VOLTAGE: 8V@40A; CONFIGURATION: 2 Diffpair; CaptureCellPackProp: D_ESD_DIFFPAIRB; DEVICE_TYPENAME: D_ESD_DIFFPAIR_DUAL-TPD4E02B04DQAR2DIFFPAIRBI-DIRECTIONAL6V001UA67V8V40A037PF090-0296-000-090-0296-000; DRAWING: @P3768_A04_LIB.P3768_A04(SCH_1):PAGE16; MAX_REVERSE_LEAKAGE_CURRENT: 0.01uA; MAX_REVERSE_VOLTAGE: 6V; NO_XNET_CONNECTION: 1; NV_NAME: TPD4E02B04DQAR; NV_PN: 090-0296-000; PACK_TYPE: DUAL; PATH: I15; PHYS_PAGE: 16; POLARITY: Bi-Directional; ROT: 0; SEC: 2; VER: 2; XY: (-3650,950)
J7 = CON_USB3#1: ANGLE: 90; ASSEMBLY: USB3_TYPEA; CDS_LIB: electro_mechanic; CDS_PART_NAME: CON_USB3_TYPEA_27PIN-G3509CE04C-008-H,RECEPTACLE,2MM,90,YES,YES,YES,NO,YES,30V,1.8 A,065-0738-000; CDS_PHYS_PART_NAME: CON_USB3_TYPEA_27PIN-G3509CE04C-008-H,RECEPTACLE,2MM,90,YES,YES,YES,NO,YES,30V,1.8 A,065-0738-000-065-0738-000; CDS_SEC: 1; DEVICE_TYPENAME: CON_USB3_TYPEA_27PIN-G3509CE04C-008-HRECEPTACLE2MM90YESYESYESNOYES30V18A065-0738-000-065-0738-000; DRAWING: @P3768_A04_LIB.P3768_A04(SCH_1):PAGE16; EMI_GROUND_TAB: NO; GENDER: Receptacle; LATCHING: YES; MAX_CURRENT: 1.8 A; MAX_VOLTAGE: 30v; NV_NAME: G3509CE04C-008-H; NV_PN: 065-0738-000; PACK_TYPE: TYPEA_27PIN; PATH: I68; PHYS_PAGE: 16; PITCH: 2mm; REFLOW: YES; ROT: 0; SEC: 1; SHIELDED: YES; SHROUDED: YES; VER: 14; XY: (-1100,3200)
L2 = L_CMF_4P: ASSEMBLY: USB3_TYPEA; CDS_LIB: discrete; CDS_PART_NAME: L_CMF_4P_SMDA_012X010-90OHM,[ ],25%,0.2A,0.4OHM,[ ],102-0037-000; CDS_PHYS_PART_NAME: L_CMF_4P_SMDA_012X010-90OHM,[ ],25%,0.2A,0.4OHM,[ ],102-0037-000-102-0037-000,90OHM; CDS_SEC: 1; DC_RESISTANCE: 0.4ohm; DEVICE_TYPENAME: L_CMF_4P_SMDA_012X010-90OHM2502A04OHM102-0037-000-102-0037-00090OHM; DRAWING: @P3768_A04_LIB.P3768_A04(SCH_1):PAGE16; MAT: [ ]; MAX_CURRENT: 0.2A; NO_XNET_CONNECTION: 1; NV_NAME: [ ]; NV_PN: 102-0037-000; PACK_TYPE: SMDA_012X010; PATH: I91; PHYS_PAGE: 16; PLACEMENT_NOTE: CoLayout with R167, R169; ROT: 6; SEC: 1; SEC_TYPE: SMDA_012X010; SIGNAL_MODEL: nv_ind_cmf_4p; SKU: DNI; TOL: 25%; VER: 1; XY: (-6700,5050)
L8 = L_CMF_4P: ASSEMBLY: USB3_TYPEA; CDS_LIB: discrete; CDS_PART_NAME: L_CMF_4P_SMDA_012X010-90OHM,[ ],25%,0.2A,0.4OHM,[ ],102-0037-000; CDS_PHYS_PART_NAME: L_CMF_4P_SMDA_012X010-90OHM,[ ],25%,0.2A,0.4OHM,[ ],102-0037-000-102-0037-000,90OHM; CDS_SEC: 1; DC_RESISTANCE: 0.4ohm; DEVICE_TYPENAME: L_CMF_4P_SMDA_012X010-90OHM2502A04OHM102-0037-000-102-0037-00090OHM; DRAWING: @P3768_A04_LIB.P3768_A04(SCH_1):PAGE16; MAT: [ ]; MAX_CURRENT: 0.2A; NO_XNET_CONNECTION: 1; NV_NAME: [ ]; NV_PN: 102-0037-000; PACK_TYPE: SMDA_012X010; PATH: I94; PHYS_PAGE: 16; PLACEMENT_NOTE: CoLayout with R167, R169; ROT: 0; SEC: 1; SEC_TYPE: SMDA_012X010; SIGNAL_MODEL: nv_ind_cmf_4p; SKU: DNI; TOL: 25%; VER: 1; XY: (-6700,2600)
L24 = L_CMF_4P: ASSEMBLY: USB3_TYPEA; CDS_LIB: discrete; CDS_PART_NAME: L_CMF_4P_SMDA_012X010-90OHM,[ ],25%,0.2A,0.4OHM,[ ],102-0037-000; CDS_PHYS_PART_NAME: L_CMF_4P_SMDA_012X010-90OHM,[ ],25%,0.2A,0.4OHM,[ ],102-0037-000-102-0037-000,90OHM; CDS_SEC: 1; DC_RESISTANCE: 0.4ohm; DEVICE_TYPENAME: L_CMF_4P_SMDA_012X010-90OHM2502A04OHM102-0037-000-102-0037-00090OHM; DRAWING: @P3768_A04_LIB.P3768_A04(SCH_1):PAGE16; MAT: [ ]; MAX_CURRENT: 0.2A; NO_XNET_CONNECTION: 1; NV_NAME: [ ]; NV_PN: 102-0037-000; PACK_TYPE: SMDA_012X010; PATH: I95; PHYS_PAGE: 16; PLACEMENT_NOTE: CoLayout with R167, R169; ROT: 4; SEC: 1; SEC_TYPE: SMDA_012X010; SIGNAL_MODEL: nv_ind_cmf_4p; SKU: DNI; TOL: 25%; VER: 1; XY: (-6700,2050)
L25 = L_CMF_4P: ASSEMBLY: USB3_TYPEA; CDS_LIB: discrete; CDS_PART_NAME: L_CMF_4P_SMDA_012X010-90OHM,[ ],25%,0.2A,0.4OHM,[ ],102-0037-000; CDS_PHYS_PART_NAME: L_CMF_4P_SMDA_012X010-90OHM,[ ],25%,0.2A,0.4OHM,[ ],102-0037-000-102-0037-000,90OHM; CDS_SEC: 1; DC_RESISTANCE: 0.4ohm; DEVICE_TYPENAME: L_CMF_4P_SMDA_012X010-90OHM2502A04OHM102-0037-000-102-0037-00090OHM; DRAWING: @P3768_A04_LIB.P3768_A04(SCH_1):PAGE16; MAT: [ ]; MAX_CURRENT: 0.2A; NO_XNET_CONNECTION: 1; NV_NAME: [ ]; NV_PN: 102-0037-000; PACK_TYPE: SMDA_012X010; PATH: I92; PHYS_PAGE: 16; PLACEMENT_NOTE: CoLayout with R167, R169; ROT: 4; SEC: 1; SEC_TYPE: SMDA_012X010; SIGNAL_MODEL: nv_ind_cmf_4p; SKU: DNI; TOL: 25%; VER: 1; XY: (-6700,4500)
L26 = L_CMF_4P: ASSEMBLY: USB3_TYPEA; CDS_LIB: discrete; CDS_PART_NAME: L_CMF_4P_SMDA_012X010-90OHM,[ ],25%,0.2A,0.4OHM,[ ],102-0037-000; CDS_PHYS_PART_NAME: L_CMF_4P_SMDA_012X010-90OHM,[ ],25%,0.2A,0.4OHM,[ ],102-0037-000-102-0037-000,90OHM; CDS_SEC: 1; DC_RESISTANCE: 0.4ohm; DEVICE_TYPENAME: L_CMF_4P_SMDA_012X010-90OHM2502A04OHM102-0037-000-102-0037-00090OHM; DRAWING: @P3768_A04_LIB.P3768_A04(SCH_1):PAGE16; MAT: [ ]; MAX_CURRENT: 0.2A; NO_XNET_CONNECTION: 1; NV_NAME: [ ]; NV_PN: 102-0037-000; PACK_TYPE: SMDA_012X010; PATH: I93; PHYS_PAGE: 16; PLACEMENT_NOTE: CoLayout with R167, R169; ROT: 4; SEC: 1; SEC_TYPE: SMDA_012X010; SIGNAL_MODEL: nv_ind_cmf_4p; SKU: DNI; TOL: 25%; VER: 1; XY: (-6700,3950)
L27 = L_CMF_4P: ASSEMBLY: USB3_TYPEA; CDS_LIB: discrete; CDS_PART_NAME: L_CMF_4P_SMDA_012X010-90OHM,[ ],25%,0.2A,0.4OHM,[ ],102-0037-000; CDS_PHYS_PART_NAME: L_CMF_4P_SMDA_012X010-90OHM,[ ],25%,0.2A,0.4OHM,[ ],102-0037-000-102-0037-000,90OHM; CDS_SEC: 1; DC_RESISTANCE: 0.4ohm; DEVICE_TYPENAME: L_CMF_4P_SMDA_012X010-90OHM2502A04OHM102-0037-000-102-0037-00090OHM; DRAWING: @P3768_A04_LIB.P3768_A04(SCH_1):PAGE16; MAT: [ ]; MAX_CURRENT: 0.2A; NO_XNET_CONNECTION: 1; NV_NAME: [ ]; NV_PN: 102-0037-000; PACK_TYPE: SMDA_012X010; PATH: I96; PHYS_PAGE: 16; PLACEMENT_NOTE: CoLayout with R167, R169; ROT: 4; SEC: 1; SEC_TYPE: SMDA_012X010; SIGNAL_MODEL: nv_ind_cmf_4p; SKU: DNI; TOL: 25%; VER: 1; XY: (-6700,1500)
R44 = R#1: ASSEMBLY: USB3_TYPEA; CDS_LIB: discrete; CDS_PART_NAME: R_0402-0OHM,0.05 OHM,62.5MW,195-2655-000; CDS_PHYS_PART_NAME: R_0402-0OHM,0.05 OHM,62.5MW,195-2655-000-0OHM,195-2655-000; CDS_SEC: 1; CHIPS_PART_NAME: R; DEVICE_TYPENAME: R_0402-0OHM005OHM625MW195-2655-000-0OHM195-2655-000; DRAWING: @P3768_A04_LIB.P3768_A04(SCH_1):PAGE16; MAX_WATTAGE: 62.5mW; NV_PN: 195-2655-000; PATH: I82; PHYS_PAGE: 16; PLACEMENT_NOTE: CoLayout with L10; ROT: 0; SEC: 1; SIGNAL_MODEL: DEFAULT_RESISTOR_0.001OHM_2_1; TOL: 0.05 ohm; VER: 1; XY: (-6700,2750)
R45 = R#1: ASSEMBLY: USB3_TYPEA; CDS_LIB: discrete; CDS_PART_NAME: R_0402-0OHM,0.05 OHM,62.5MW,195-2655-000; CDS_PHYS_PART_NAME: R_0402-0OHM,0.05 OHM,62.5MW,195-2655-000-0OHM,195-2655-000; CDS_SEC: 1; CHIPS_PART_NAME: R; DEVICE_TYPENAME: R_0402-0OHM005OHM625MW195-2655-000-0OHM195-2655-000; DRAWING: @P3768_A04_LIB.P3768_A04(SCH_1):PAGE16; MAX_WATTAGE: 62.5mW; NV_PN: 195-2655-000; PATH: I84; PHYS_PAGE: 16; PLACEMENT_NOTE: CoLayout with L10; ROT: 0; SEC: 1; SIGNAL_MODEL: DEFAULT_RESISTOR_0.001OHM_2_1; TOL: 0.05 ohm; VER: 1; XY: (-6700,2450)
R46 = R#1: ASSEMBLY: USB3_TYPEA; CDS_LIB: discrete; CDS_PART_NAME: R_0402-0OHM,0.05 OHM,62.5MW,195-2655-000; CDS_PHYS_PART_NAME: R_0402-0OHM,0.05 OHM,62.5MW,195-2655-000-0OHM,195-2655-000; CDS_SEC: 1; CHIPS_PART_NAME: R; DEVICE_TYPENAME: R_0402-0OHM005OHM625MW195-2655-000-0OHM195-2655-000; DRAWING: @P3768_A04_LIB.P3768_A04(SCH_1):PAGE16; MAX_WATTAGE: 62.5mW; NV_PN: 195-2655-000; PATH: I75; PHYS_PAGE: 16; PLACEMENT_NOTE: CoLayout with L10; ROT: 0; SEC: 1; SIGNAL_MODEL: DEFAULT_RESISTOR_0.001OHM_2_1; TOL: 0.05 ohm; VER: 1; XY: (-6700,5200)
R47 = R#1: ASSEMBLY: USB3_TYPEA; CDS_LIB: discrete; CDS_PART_NAME: R_0402-0OHM,0.05 OHM,62.5MW,195-2655-000; CDS_PHYS_PART_NAME: R_0402-0OHM,0.05 OHM,62.5MW,195-2655-000-0OHM,195-2655-000; CDS_SEC: 1; CHIPS_PART_NAME: R; DEVICE_TYPENAME: R_0402-0OHM005OHM625MW195-2655-000-0OHM195-2655-000; DRAWING: @P3768_A04_LIB.P3768_A04(SCH_1):PAGE16; MAX_WATTAGE: 62.5mW; NV_PN: 195-2655-000; PATH: I73; PHYS_PAGE: 16; PLACEMENT_NOTE: CoLayout with L10; ROT: 0; SEC: 1; SIGNAL_MODEL: DEFAULT_RESISTOR_0.001OHM_2_1; TOL: 0.05 ohm; VER: 1; XY: (-6700,4900)
R174 = R: ASSEMBLY: USB3_TYPEA; CDS_LIB: discrete; CDS_PART_NAME: R_0402-10K,5 %,62.5MW,195-0486-000; CDS_PHYS_PART_NAME: R_0402-10K,5 %,62.5MW,195-0486-000-10K,195-0486-000; CDS_SEC: 1; DEVICE_TYPENAME: R_0402-10K5625MW195-0486-000-10K195-0486-000; DRAWING: @P3768_A04_LIB.P3768_A04(SCH_1):PAGE16; MAX_WATTAGE: 62.5mW; NV_PN: 195-0486-000; PATH: I48; PHYS_PAGE: 16; PSPICETEMPLATE: X^@REFDES  %1    %2   @NV_PN; ROT: 0; SEC: 1; SIGNAL_MODEL: nv_res; TOL: 5 %; VER: 2; XY: (-7800,6050)
R214 = R#1: ASSEMBLY: USB3_TYPEA; CDS_LIB: discrete; CDS_PART_NAME: R_0402-0OHM,0.05 OHM,62.5MW,195-2655-000; CDS_PHYS_PART_NAME: R_0402-0OHM,0.05 OHM,62.5MW,195-2655-000-0OHM,195-2655-000; CDS_SEC: 1; CHIPS_PART_NAME: R; DEVICE_TYPENAME: R_0402-0OHM005OHM625MW195-2655-000-0OHM195-2655-000; DRAWING: @P3768_A04_LIB.P3768_A04(SCH_1):PAGE16; MAX_WATTAGE: 62.5mW; NV_PN: 195-2655-000; PATH: I85; PHYS_PAGE: 16; PLACEMENT_NOTE: CoLayout with L10; ROT: 0; SEC: 1; SIGNAL_MODEL: DEFAULT_RESISTOR_0.001OHM_2_1; TOL: 0.05 ohm; VER: 1; XY: (-6700,2200)
R215 = R#1: ASSEMBLY: USB3_TYPEA; CDS_LIB: discrete; CDS_PART_NAME: R_0402-0OHM,0.05 OHM,62.5MW,195-2655-000; CDS_PHYS_PART_NAME: R_0402-0OHM,0.05 OHM,62.5MW,195-2655-000-0OHM,195-2655-000; CDS_SEC: 1; CHIPS_PART_NAME: R; DEVICE_TYPENAME: R_0402-0OHM005OHM625MW195-2655-000-0OHM195-2655-000; DRAWING: @P3768_A04_LIB.P3768_A04(SCH_1):PAGE16; MAX_WATTAGE: 62.5mW; NV_PN: 195-2655-000; PATH: I87; PHYS_PAGE: 16; PLACEMENT_NOTE: CoLayout with L10; ROT: 0; SEC: 1; SIGNAL_MODEL: DEFAULT_RESISTOR_0.001OHM_2_1; TOL: 0.05 ohm; VER: 1; XY: (-6700,1900)
R216 = R#1: ASSEMBLY: USB3_TYPEA; CDS_LIB: discrete; CDS_PART_NAME: R_0402-0OHM,0.05 OHM,62.5MW,195-2655-000; CDS_PHYS_PART_NAME: R_0402-0OHM,0.05 OHM,62.5MW,195-2655-000-0OHM,195-2655-000; CDS_SEC: 1; CHIPS_PART_NAME: R; DEVICE_TYPENAME: R_0402-0OHM005OHM625MW195-2655-000-0OHM195-2655-000; DRAWING: @P3768_A04_LIB.P3768_A04(SCH_1):PAGE16; MAX_WATTAGE: 62.5mW; NV_PN: 195-2655-000; PATH: I76; PHYS_PAGE: 16; PLACEMENT_NOTE: CoLayout with L10; ROT: 0; SEC: 1; SIGNAL_MODEL: DEFAULT_RESISTOR_0.001OHM_2_1; TOL: 0.05 ohm; VER: 1; XY: (-6700,4650)
R217 = R#1: ASSEMBLY: USB3_TYPEA; CDS_LIB: discrete; CDS_PART_NAME: R_0402-0OHM,0.05 OHM,62.5MW,195-2655-000; CDS_PHYS_PART_NAME: R_0402-0OHM,0.05 OHM,62.5MW,195-2655-000-0OHM,195-2655-000; CDS_SEC: 1; CHIPS_PART_NAME: R; DEVICE_TYPENAME: R_0402-0OHM005OHM625MW195-2655-000-0OHM195-2655-000; DRAWING: @P3768_A04_LIB.P3768_A04(SCH_1):PAGE16; MAX_WATTAGE: 62.5mW; NV_PN: 195-2655-000; PATH: I78; PHYS_PAGE: 16; PLACEMENT_NOTE: CoLayout with L10; ROT: 0; SEC: 1; SIGNAL_MODEL: DEFAULT_RESISTOR_0.001OHM_2_1; TOL: 0.05 ohm; VER: 1; XY: (-6700,4350)
R218 = R#1: ASSEMBLY: USB3_TYPEA; CDS_LIB: discrete; CDS_PART_NAME: R_0402-0OHM,0.05 OHM,62.5MW,195-2655-000; CDS_PHYS_PART_NAME: R_0402-0OHM,0.05 OHM,62.5MW,195-2655-000-0OHM,195-2655-000; CDS_SEC: 1; CHIPS_PART_NAME: R; DEVICE_TYPENAME: R_0402-0OHM005OHM625MW195-2655-000-0OHM195-2655-000; DRAWING: @P3768_A04_LIB.P3768_A04(SCH_1):PAGE16; MAX_WATTAGE: 62.5mW; NV_PN: 195-2655-000; PATH: I79; PHYS_PAGE: 16; PLACEMENT_NOTE: CoLayout with L10; ROT: 0; SEC: 1; SIGNAL_MODEL: DEFAULT_RESISTOR_0.001OHM_2_1; TOL: 0.05 ohm; VER: 1; XY: (-6700,4100)
R219 = R#1: ASSEMBLY: USB3_TYPEA; CDS_LIB: discrete; CDS_PART_NAME: R_0402-0OHM,0.05 OHM,62.5MW,195-2655-000; CDS_PHYS_PART_NAME: R_0402-0OHM,0.05 OHM,62.5MW,195-2655-000-0OHM,195-2655-000; CDS_SEC: 1; CHIPS_PART_NAME: R; DEVICE_TYPENAME: R_0402-0OHM005OHM625MW195-2655-000-0OHM195-2655-000; DRAWING: @P3768_A04_LIB.P3768_A04(SCH_1):PAGE16; MAX_WATTAGE: 62.5mW; NV_PN: 195-2655-000; PATH: I81; PHYS_PAGE: 16; PLACEMENT_NOTE: CoLayout with L10; ROT: 0; SEC: 1; SIGNAL_MODEL: DEFAULT_RESISTOR_0.001OHM_2_1; TOL: 0.05 ohm; VER: 1; XY: (-6700,3800)
R220 = R#1: ASSEMBLY: USB3_TYPEA; CDS_LIB: discrete; CDS_PART_NAME: R_0402-0OHM,0.05 OHM,62.5MW,195-2655-000; CDS_PHYS_PART_NAME: R_0402-0OHM,0.05 OHM,62.5MW,195-2655-000-0OHM,195-2655-000; CDS_SEC: 1; CHIPS_PART_NAME: R; DEVICE_TYPENAME: R_0402-0OHM005OHM625MW195-2655-000-0OHM195-2655-000; DRAWING: @P3768_A04_LIB.P3768_A04(SCH_1):PAGE16; MAX_WATTAGE: 62.5mW; NV_PN: 195-2655-000; PATH: I88; PHYS_PAGE: 16; PLACEMENT_NOTE: CoLayout with L10; ROT: 0; SEC: 1; SIGNAL_MODEL: DEFAULT_RESISTOR_0.001OHM_2_1; TOL: 0.05 ohm; VER: 1; XY: (-6700,1650)
R221 = R#1: ASSEMBLY: USB3_TYPEA; CDS_LIB: discrete; CDS_PART_NAME: R_0402-0OHM,0.05 OHM,62.5MW,195-2655-000; CDS_PHYS_PART_NAME: R_0402-0OHM,0.05 OHM,62.5MW,195-2655-000-0OHM,195-2655-000; CDS_SEC: 1; CHIPS_PART_NAME: R; DEVICE_TYPENAME: R_0402-0OHM005OHM625MW195-2655-000-0OHM195-2655-000; DRAWING: @P3768_A04_LIB.P3768_A04(SCH_1):PAGE16; MAX_WATTAGE: 62.5mW; NV_PN: 195-2655-000; PATH: I90; PHYS_PAGE: 16; PLACEMENT_NOTE: CoLayout with L10; ROT: 0; SEC: 1; SIGNAL_MODEL: DEFAULT_RESISTOR_0.001OHM_2_1; TOL: 0.05 ohm; VER: 1; XY: (-6700,1350)
U25 = U_SW_LOAD: ASSEMBLY: USB3_TYPEA; CDS_LIB: analog; CDS_PART_NAME: U_SW_LOAD_SOT23_5B-AP22811AW5-7,0MV..5.5V,2.7V..5.5V,9999A,SWITCH,115-2766-000; CDS_PHYS_PART_NAME: U_SW_LOAD_SOT23_5B-AP22811AW5-7,0MV..5.5V,2.7V..5.5V,9999A,SWITCH,115-2766-000-115-2766-000; CDS_SEC: 1; DEVICE_TYPENAME: U_SW_LOAD_SOT23_5B-AP22811AW5-70MV55V27V55V9999ASWITCH115-2766-000-115-2766-000; DRAWING: @P3768_A04_LIB.P3768_A04(SCH_1):PAGE16; MAX_CURRENT: 9999A; MAX_VOLTAGE: 2.7V..5.5V; NV_NAME: AP22811AW5-7; NV_PN: 115-2766-000; OUTPUT_VOLTAGE: 0mV..5.5V; PACK_TYPE: SOT23_5B; PATH: I55; PHYS_PAGE: 16; ROT: 0; SEC: 1; TYPE: Switch; VER: 7; XY: (-6850,6250)

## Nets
GND: C127.2 C158.2 C160.2 C172.2 C173.2 C376.2 D8.3(GND1) D9.3(GND1) D10.3(GND1) D11.3(GND1) D12.3(GND1) D13.3(GND1) J6.4(GND1) J6.7(GND2) J6.13(GND3) J6.16(GND4) J6.19(MT1) J6.20(MT2) J6.21(MT3) J6.22(MT4) J6.23(MT5) J6.24(MT6) J6.25(MT7) J6.26(MT8) J6.27(MT9) J7.4(GND1) J7.7(GND2) J7.13(GND3) J7.16(GND4) J7.19(MT1) J7.20(MT2) J7.21(MT3) J7.22(MT4) J7.23(MT5) J7.24(MT6) J7.25(MT7) J7.26(MT8) J7.27(MT9) R40.2 R174.2 U21.2(GND) U25.2(GND) ; also on sheet 1 2 3 4 5 6 7 8 11 12 13 14 15 16 17 18 19 21 25
VDD_5V_SYS: C127.1 C158.1 U21.5(IN) U25.5(IN) ; also on sheet 1 2 8 11 12 13 14 15 16 17 21
VDD_VBUS_A: C172.1 C376.1 J6.1(VBUS0) J6.10(VBUS1) U21.1(OUT)
VDD_VBUS_B: C160.1 C173.1 J7.1(VBUS0) J7.10(VBUS1) U25.1(OUT)
DSP1_DN: L101.2 R167.1 ; also on sheet 11
DSP1_DP: L101.1 R169.1 ; also on sheet 11
DSP1_SSRX_N: L20.3 R206.1 ; also on sheet 11
DSP1_SSRX_P: L20.4 R207.1 ; also on sheet 11
DSP1_SSTX_N: C66.1 ; also on sheet 11
DSP1_SSTX_P: C64.1 ; also on sheet 11
DSP2_DN: L1.2 R41.1 ; also on sheet 11
DSP2_DP: L1.1 R42.1 ; also on sheet 11
DSP2_SSRX_N: L21.4 R208.1 ; also on sheet 11
DSP2_SSRX_P: L21.3 R209.1 ; also on sheet 11
DSP2_SSTX_N: C67.1 ; also on sheet 11
DSP2_SSTX_P: C65.1 ; also on sheet 11
DSP3_DN: L2.2 R46.1 ; also on sheet 11
DSP3_DP: L2.1 R47.1 ; also on sheet 11
DSP3_SSRX_N: L25.3 R216.1 ; also on sheet 11
DSP3_SSRX_P: L25.4 R217.1 ; also on sheet 11
DSP3_SSTX_N: C74.1 ; also on sheet 11
DSP3_SSTX_P: C72.1 ; also on sheet 11
DSP4_DN: L8.1 R44.1 ; also on sheet 11
DSP4_DP: L8.2 R45.1 ; also on sheet 11
DSP4_SSRX_N: L24.3 R214.1 ; also on sheet 11
DSP4_SSRX_P: L24.4 R215.1 ; also on sheet 11
DSP4_SSTX_N: C75.1 ; also on sheet 11
DSP4_SSTX_P: C73.1 ; also on sheet 11
HUB_DSP12_OCP: U21.3(OC*) ; also on sheet 11
HUB_DSP12_PWR_EN: R40.1 U21.4(EN) ; also on sheet 11
HUB_DSP34_OCP: U25.3(OC*) ; also on sheet 11
HUB_DSP34_PWR_EN: R174.1 U25.4(EN) ; also on sheet 11
USB1_A_N: D8.1(1A) D8.10(1B) J6.11(DN1) L101.3 R167.2
USB1_A_P: D8.2(2A) D8.9(2B) J6.12(DP1) L101.4 R169.2
USB1_B_N: D12.1(1A) D12.10(1B) J7.11(DN1) L2.3 R46.2
USB1_B_P: D12.2(2A) D12.9(2B) J7.12(DP1) L2.4 R47.2
USB2_A_N: D8.4(3A) D8.7(3B) J6.2(DN0) L1.3 R41.2
USB2_A_P: D8.5(4A) D8.6(4B) J6.3(DP0) L1.4 R42.2
USB2_B_N: D13.5(4A) D13.6(4B) J7.2(DN0) L8.4 R44.2
USB2_B_P: D13.4(3A) D13.7(3B) J7.3(DP0) L8.3 R45.2
USBSS1_RX_A_CON1_N: D9.2(2A) D9.9(2B) J6.14(SSRXN1) L20.2 R206.2
USBSS1_RX_A_CON1_P: D9.1(1A) D9.10(1B) J6.15(SSRXP1) L20.1 R207.2
USBSS1_TX_A_CON1_N: D10.1(1A) D10.10(1B) J6.17(SSTXN1) L22.2 R210.2
USBSS1_TX_A_CON1_P: D10.2(2A) D10.9(2B) J6.18(SSTXP1) L22.1 R211.2
USBSS2_RX_A_CON2_N: D9.4(3A) D9.7(3B) J6.5(SSRXN0) L21.1 R208.2
USBSS2_RX_A_CON2_P: D9.5(4A) D9.6(4B) J6.6(SSRXP0) L21.2 R209.2
USBSS2_TX_A_CON2_N: D10.5(4A) D10.6(4B) J6.8(SSTXN0) L23.1 R212.2
USBSS2_TX_A_CON2_P: D10.4(3A) D10.7(3B) J6.9(SSTXP0) L23.2 R213.2
USBSS2_TX_A_N: C67.2 L23.4 R212.1
USBSS2_TX_A_P: C65.2 L23.3 R213.1
USBSS_RX_B_CON1_N: D13.2(2A) D13.9(2B) J7.14(SSRXN1) L25.2 R216.2
USBSS_RX_B_CON1_P: D13.1(1A) D13.10(1B) J7.15(SSRXP1) L25.1 R217.2
USBSS_RX_B_CON2_N: D12.5(4A) D12.6(4B) J7.5(SSRXN0) L24.2 R214.2
USBSS_RX_B_CON2_P: D12.4(3A) D12.7(3B) J7.6(SSRXP0) L24.1 R215.2
USBSS_TX_A_1_N: C66.2 L22.3 R210.1
USBSS_TX_A_1_P: C64.2 L22.4 R211.1
USBSS_TX_B_1_N: C74.2 L26.3 R218.1
USBSS_TX_B_1_P: C72.2 L26.4 R219.1
USBSS_TX_B_2_N: C75.2 L27.3 R220.1
USBSS_TX_B_2_P: C73.2 L27.4 R221.1
USBSS_TX_B_CON1_N: D11.4(3A) D11.7(3B) J7.17(SSTXN1) L26.2 R218.2
USBSS_TX_B_CON1_P: D11.5(4A) D11.6(4B) J7.18(SSTXP1) L26.1 R219.2
USBSS_TX_B_CON2_N: D11.1(1A) D11.10(1B) J7.8(SSTXN0) L27.2 R220.2
USBSS_TX_B_CON2_P: D11.2(2A) D11.9(2B) J7.9(SSTXP0) L27.1 R221.2

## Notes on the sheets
sheet 9
- A
- B
- C
- D
- E
- F
- G
- H
- USB3.1 TYPE-A x2 [B]
- 1
- 1
- 2
- PCB CO-LAYOUT
- 2
- PCB CO-LAYOUT
- PCB CO-LAYOUT
- 3
- 3
- PCB CO-LAYOUT
- PCB CO-LAYOUT
- 4
- 4
- PCB CO-LAYOUT
- 5
- 5
- NVIDIA CORPORATION
- 2701 SAN TOMAS EXPRESSWAY
- SANTA CLARA, CA 95050, USA
- ASSEMBLY
- <ASSEMBLY_DESCRIPTION>
- PAGE DETAIL
- USB3.1 Type-A x2 [B]
- 600-13768-BASE-400
- NV_PN
- ALL NVIDIA DESIGN SPECIFICATIONS, REFERENCE SPECIFICATIONS, REFERENCE BOARDS, FILES, DRAWINGS, DIAGNOSTICS, LISTS AND OTHER DOCUMENTS OR INFORMATION (TOGETHER AND SEPARATELY, 'MATERIALS') ARE BEING PROVIDED 'AS IS'. THE MATERIALS MAY
- P3768-A04
- 16 OF 25
- CONTAIN KNOWN AND UNKNOWN VIOLATIONS OR DEVIATIONS OF INDUSTRY STANDARDS AND SPECIFICATIONS. NVIDIA MAKES NO WARRANTIES, EXPRESSED, IMPLIED, STATUTORY OR OTHERWISE WITH RESPECT TO THE MATERIALS OR OTHERWISE, AND EXPRESSLY DISCLAIMS ALL
- PCB REV
- PAGE
- IMPLIED WARRANTIES INCLUDING, WITHOUT LIMITATION, THE WARRANTIES OF DESIGN, OF NONINFRINGEMENT, MERCHANTABILITY OR FITNESS FOR A PARTICULAR PURPOSE, OR ARISING FROM A COURSE OF DEALING, TRADE USAGE, TRADE PRACTICE, OR INDUSTRY STANDARDS.
- BOM REV
- A
- DATE
- 27-FEB-2023
- A
- B
- C
- D
- E
- F
- G
- H
sheet 10
- A
- B
- C
- D
- E
- F
- G
- H
- USB3.1 TYPE-A x2 [A]
- 1
- 1
- PCB CO-LAYOUT
- 2
- 2
- PCB CO-LAYOUT
- PCB CO-LAYOUT
- 3
- 3
- PCB CO-LAYOUT
- PCB CO-LAYOUT
- 4
- 4
- PCB CO-LAYOUT
- 5
- 5
- NVIDIA CORPORATION
- 2701 SAN TOMAS EXPRESSWAY
- SANTA CLARA, CA 95050, USA
- ASSEMBLY
- <ASSEMBLY_DESCRIPTION>
- PAGE DETAIL
- USB3.1 Type-A x2 [A]
- 600-13768-BASE-400
- NV_PN
- ALL NVIDIA DESIGN SPECIFICATIONS, REFERENCE SPECIFICATIONS, REFERENCE BOARDS, FILES, DRAWINGS, DIAGNOSTICS, LISTS AND OTHER DOCUMENTS OR INFORMATION (TOGETHER AND SEPARATELY, 'MATERIALS') ARE BEING PROVIDED 'AS IS'. THE MATERIALS MAY
- P3768-A04
- 15 OF 25
- CONTAIN KNOWN AND UNKNOWN VIOLATIONS OR DEVIATIONS OF INDUSTRY STANDARDS AND SPECIFICATIONS. NVIDIA MAKES NO WARRANTIES, EXPRESSED, IMPLIED, STATUTORY OR OTHERWISE WITH RESPECT TO THE MATERIALS OR OTHERWISE, AND EXPRESSLY DISCLAIMS ALL
- PCB REV
- PAGE
- IMPLIED WARRANTIES INCLUDING, WITHOUT LIMITATION, THE WARRANTIES OF DESIGN, OF NONINFRINGEMENT, MERCHANTABILITY OR FITNESS FOR A PARTICULAR PURPOSE, OR ARISING FROM A COURSE OF DEALING, TRADE USAGE, TRADE PRACTICE, OR INDUSTRY STANDARDS.
- BOM REV
- A
- DATE
- 27-FEB-2023
- A
- B
- C
- D
- E
- F
- G
- H
